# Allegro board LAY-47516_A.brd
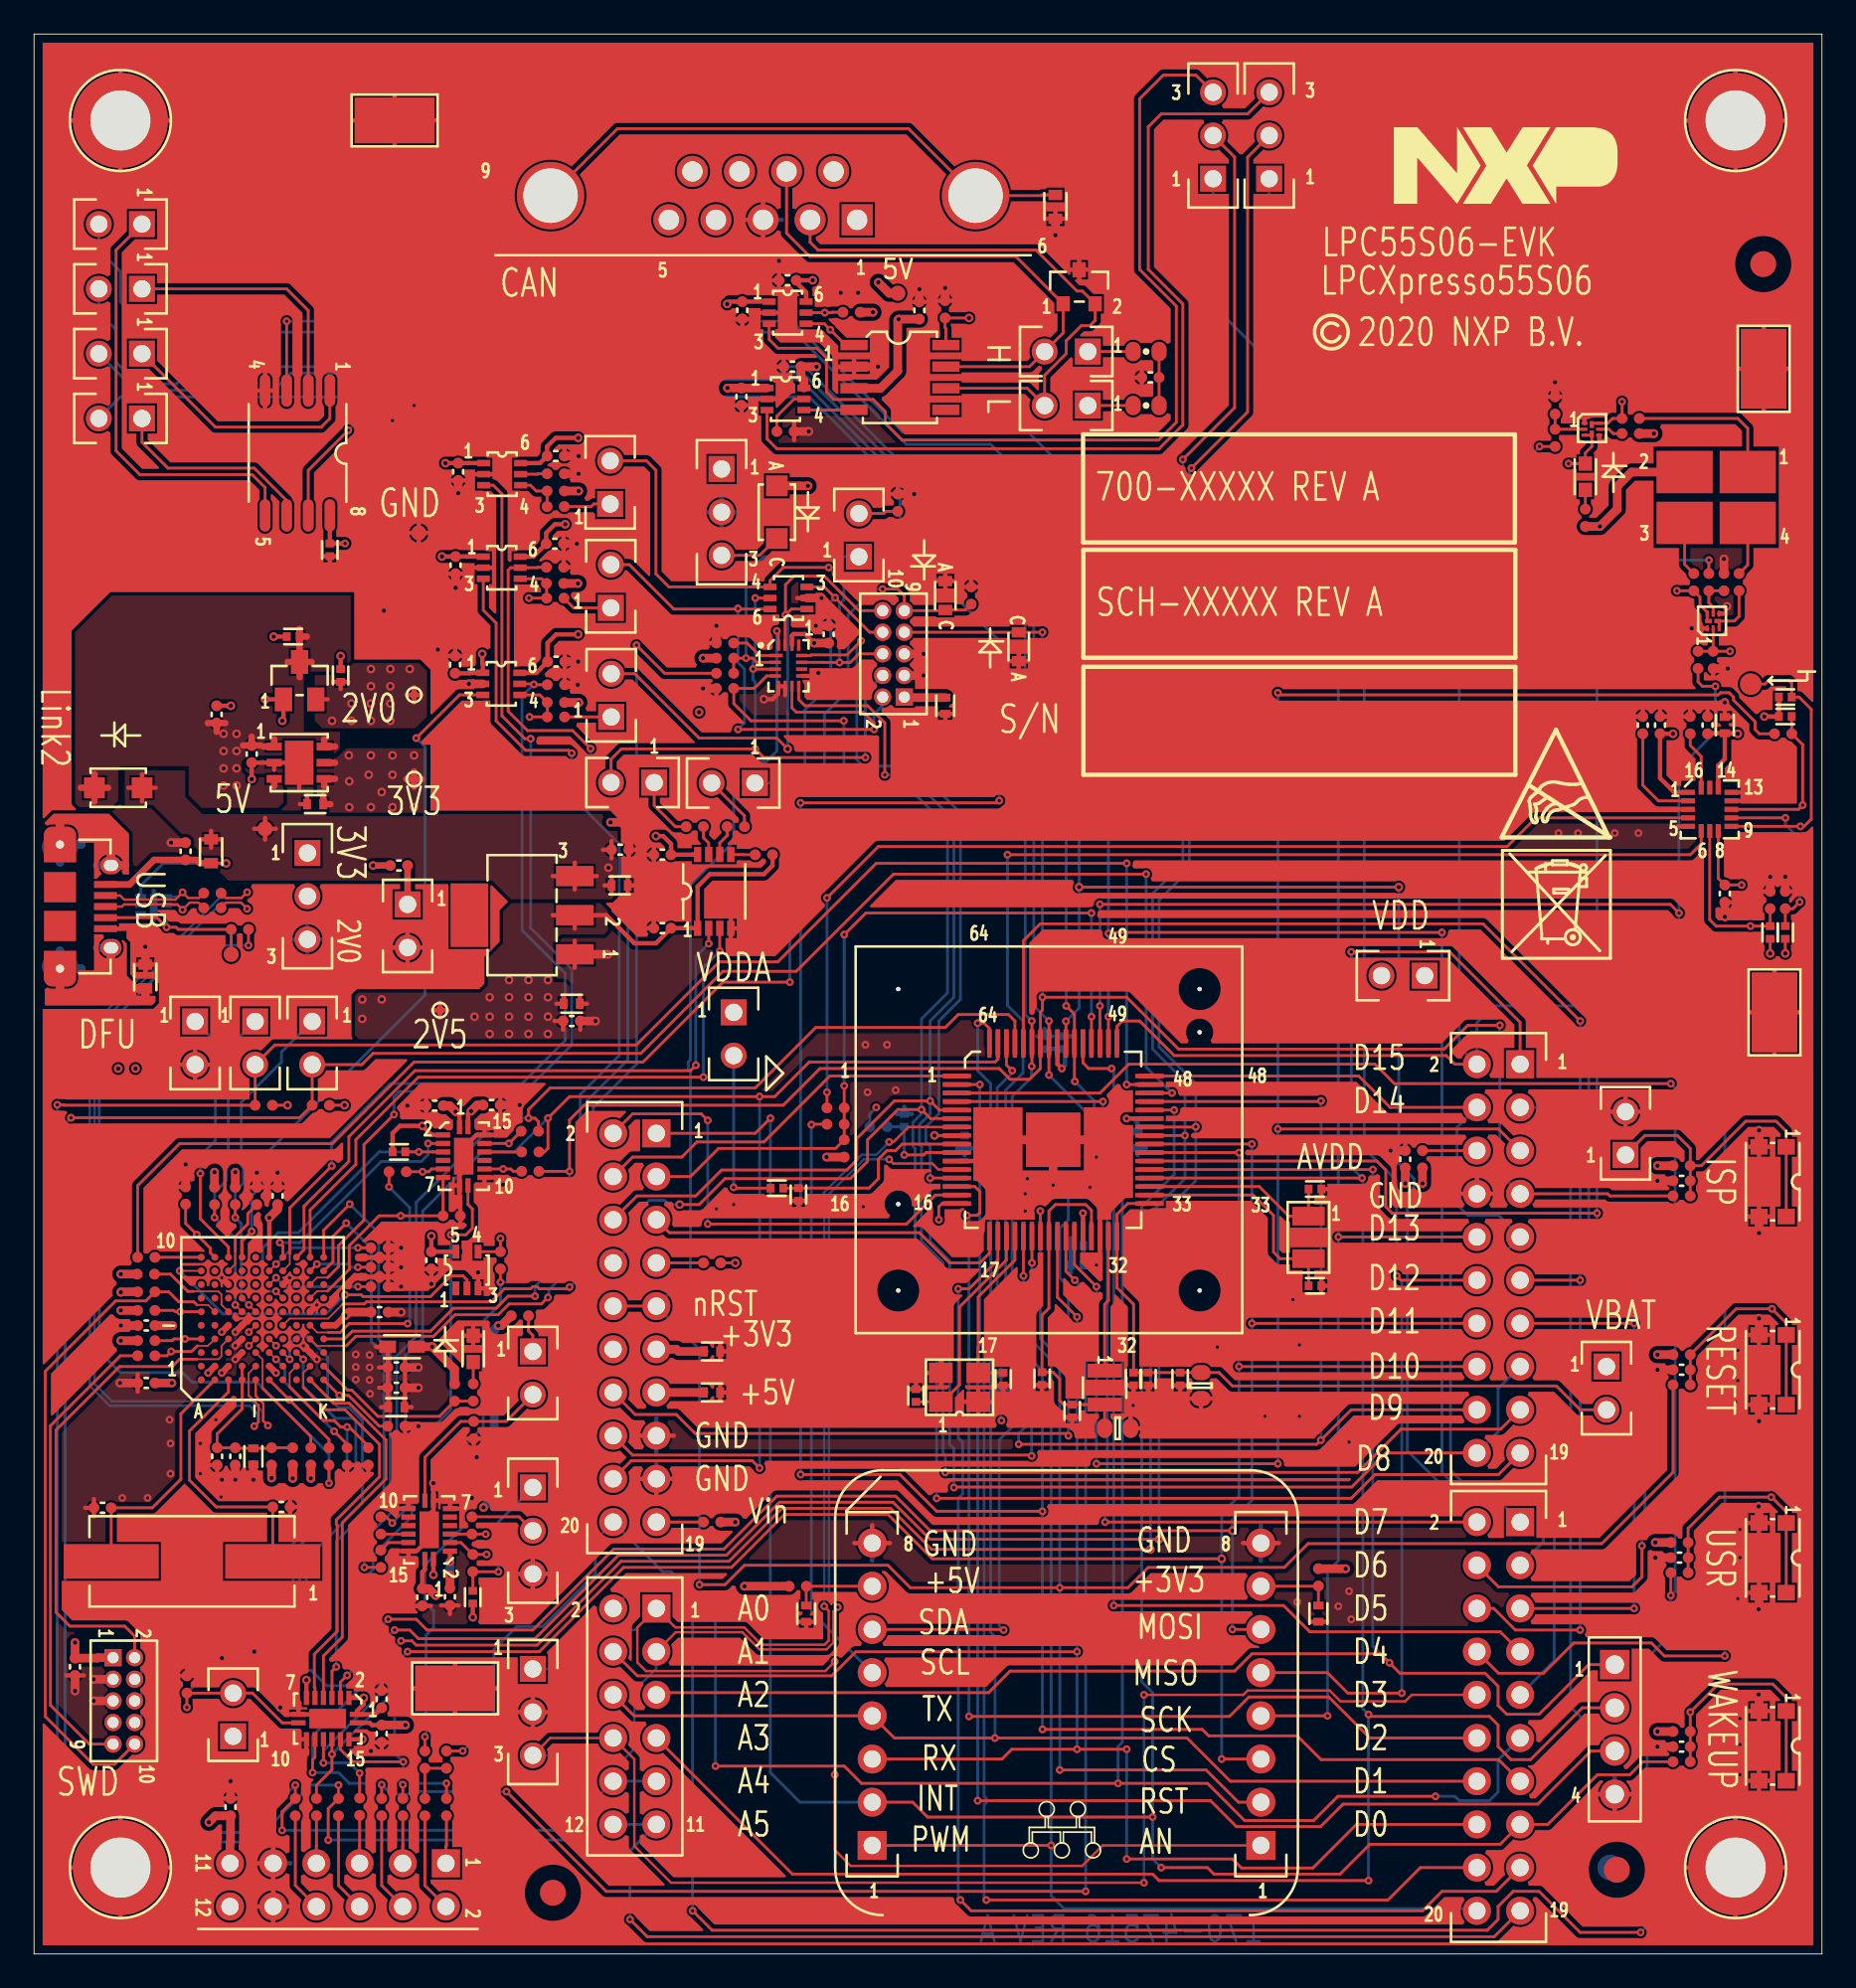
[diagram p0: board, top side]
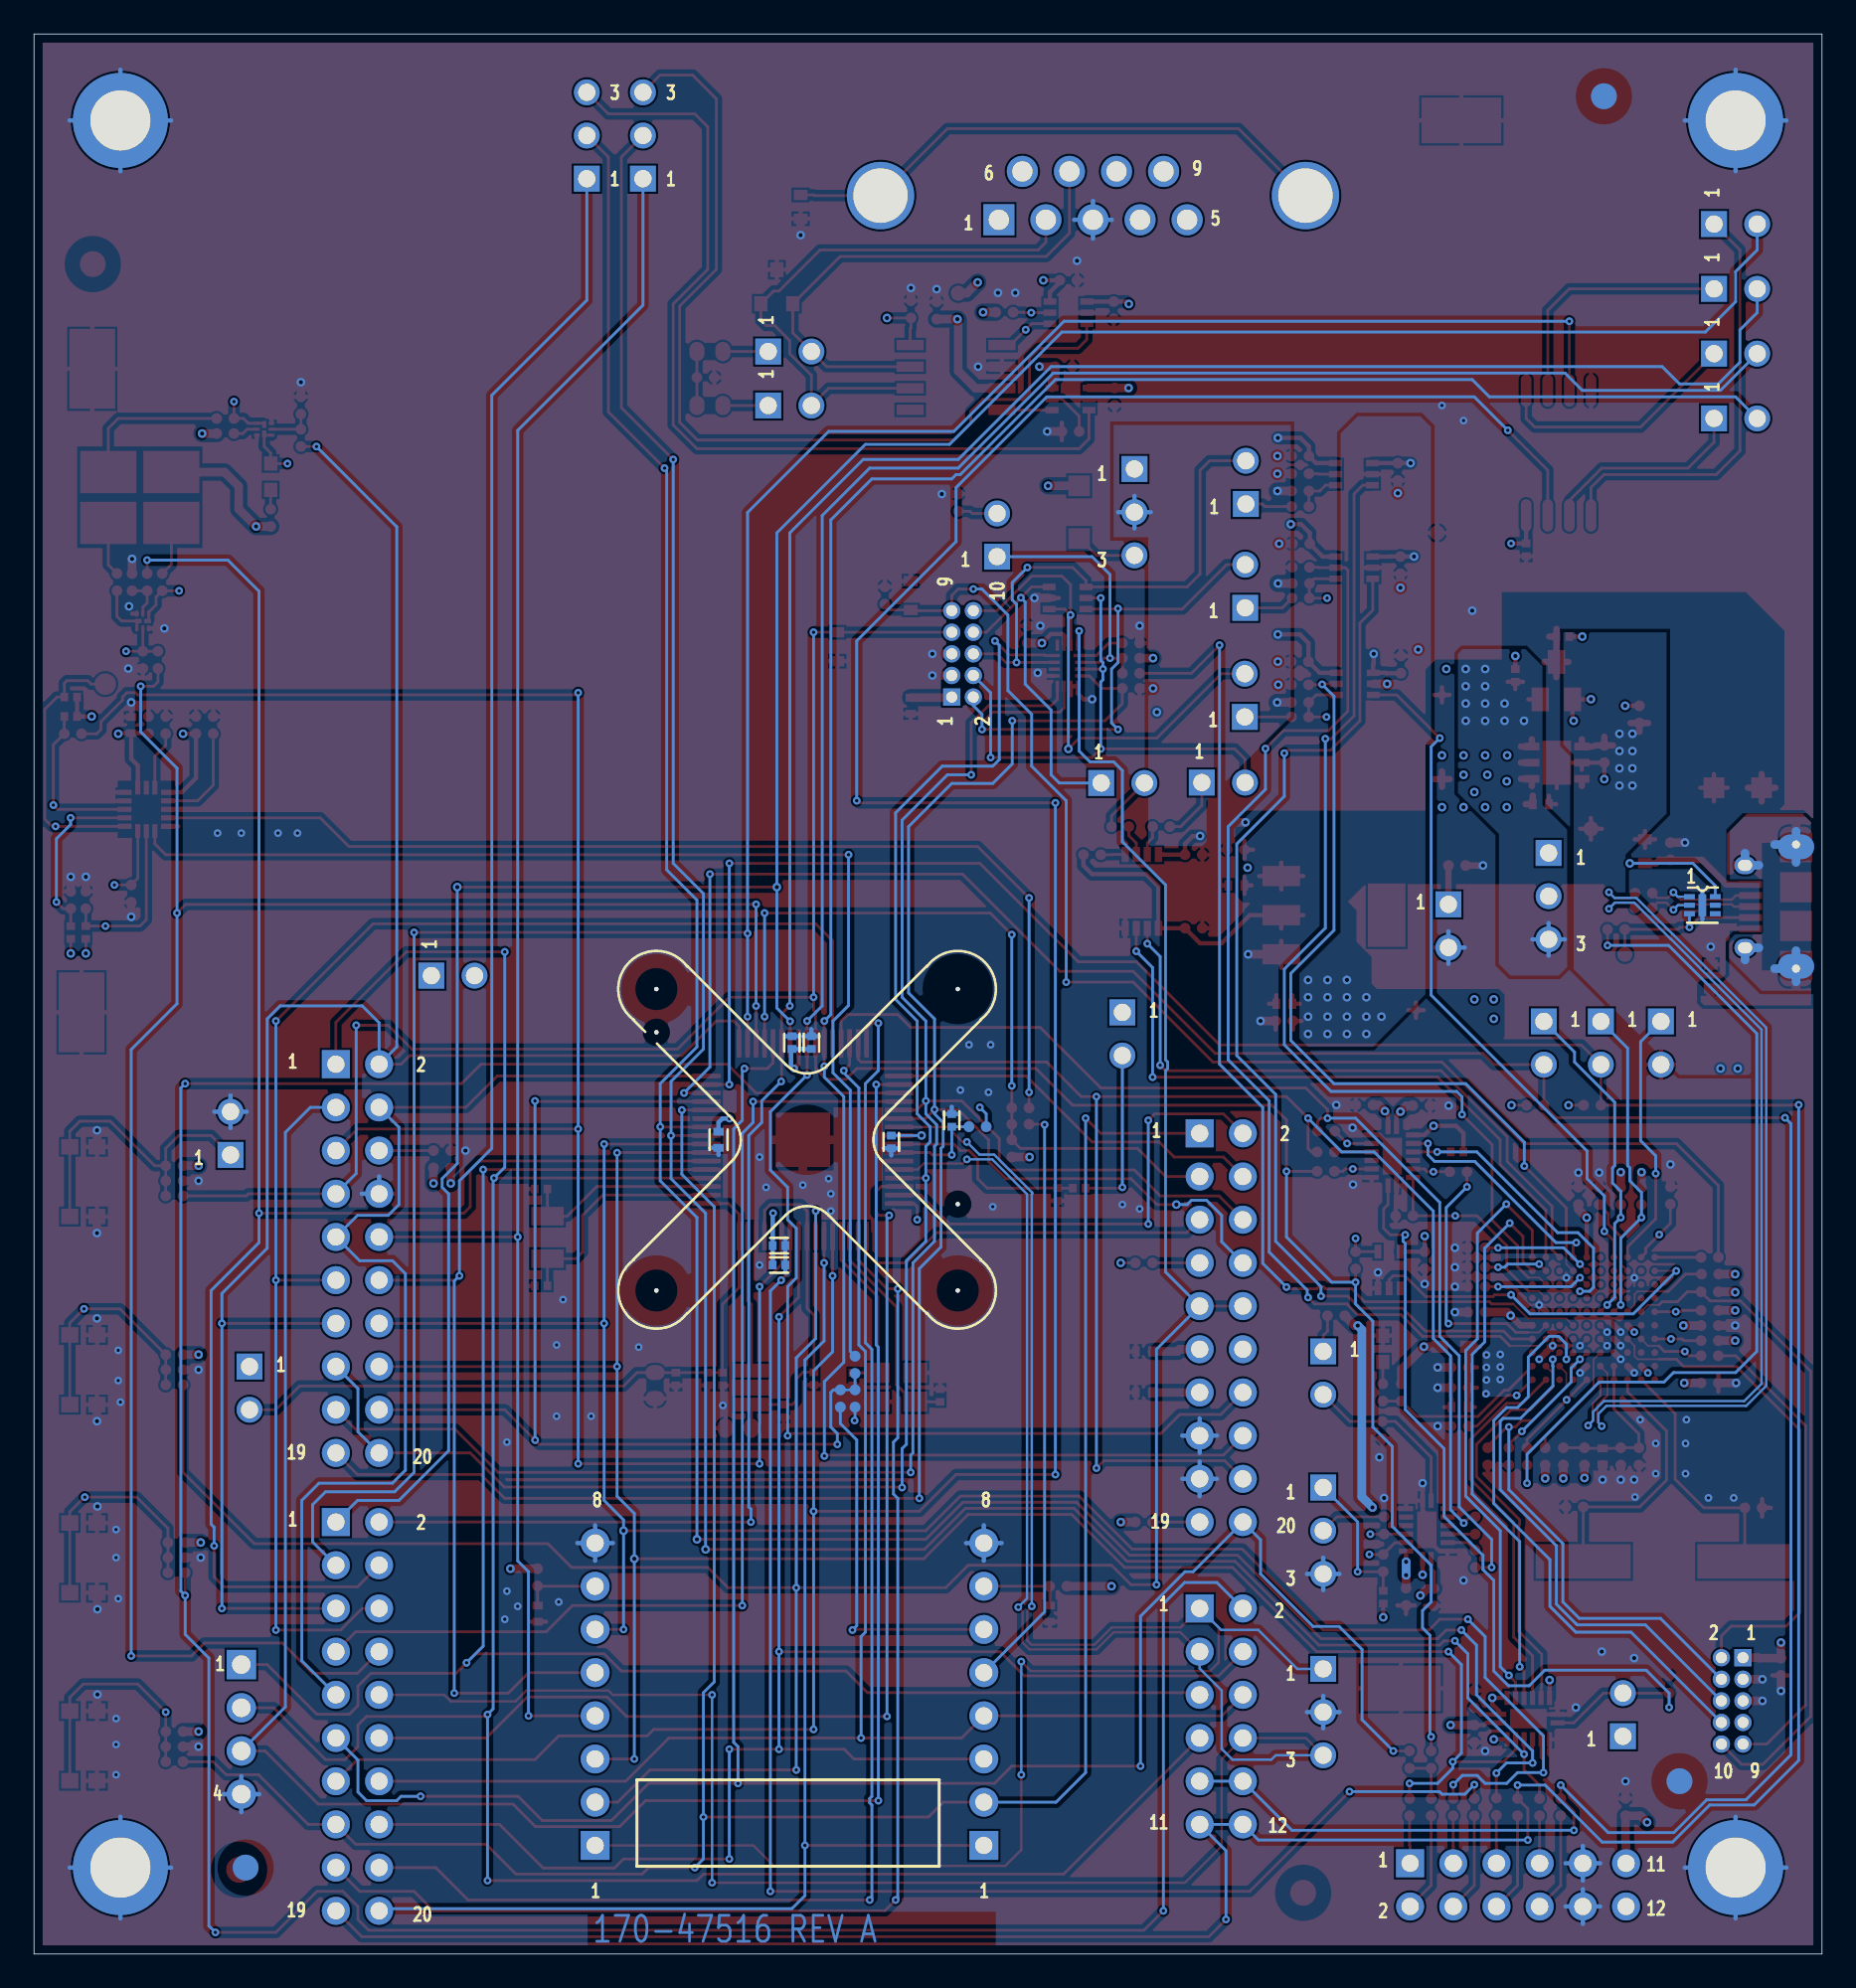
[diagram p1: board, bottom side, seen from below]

Outline 105.16 x 112.9 mm; copper layers: TOP, L2_GND_1, L3_PWR_1, BOTTOM. Coordinates in mm from the lower left corner of the outline.
Outline path: 0,112.9 0,0 105.16,0 105.16,112.9 0,112.9

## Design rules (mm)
constraint set DEFAULT: min track width 0.102
net group ARD_ADC0: nets ARD_ADC0_0_P ARD_MIK_ADC0_8_N
net group CON_DP2: nets N00991 N01033
net group FL_USB0_D: nets FL_USB0_DM FL_USB0_DP

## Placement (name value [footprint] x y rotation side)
C1  2.2UF  [CC0402_25]  8.92 64.85 90 top
C2  4.7UF  [CC0402_TOL0P15]  34.45 62.84 0 top
C3  0.1UF  [CC0402_25]  34.47 64.94 0 top
C4  4.7UF  [CC0402_TOL0P15]  31.62 55.88 0 top
C5  0.1UF  [CC0402_25]  31.62 54.86 0 top
C6  2.2UF  [CC0402_25]  12.8 70.56 270 top
C7  10uF  [CC0402_TOL0P2]  16.54 67.61 180 top
C8  2.2UF  [CC0402_25]  21.46 64.01 180 top
C10  2.2UF  [CC0402_25]  10.74 72.89 90 top
C11  1.0UF  [0402_CC]  15.24 77.47 180 top
C12  1.0UF  [0402_CC]  18.03 75.18 90 top
C18  0.1UF  [0402_CC]  61.06 31.93 270 top
C19  1.0UF  [0402_CC]  59.28 33.84 270 top
C22  0.1UF  [CC0402_25]  24.46 21.01 270 top
C23  0.1UF  [CC0402_25]  52.07 96.64 90 top
C24  0.1UF  [CC0402_25]  22.83 20.98 270 top
C25  1000pF  [CC0402_25]  65.66 92.71 180 top
C27  4.7UF  [CC0402_TOL0P15]  99.44 72.26 90 top
C28  0.1UF  [CC0402_25]  98.42 72.26 90 top
C29  0.1UF  [CC0402_25]  95.63 72.26 90 top
C30  0.1UF  [CC0402_25]  99.44 62.36 270 top
C31  0.1UF  [CC0402_25]  94.61 72.26 90 top
C32  0.01UF  [CC0402_25]  96.9 12.19 180 top
C33  0.01UF  [CC0402_25]  96.9 34.36 180 top
C34  0.01UF  [CC0402_25]  96.77 23.31 180 top
C55  10uF  [CC0402_TOL0P2]  75.54 20.02 270 top
C56  10uF  [CC0402_TOL0P2]  45.42 20.02 270 top
C57  4.7UF  [CC0402_TOL0P15]  39.88 33.02 0 top
C58  0.1UF  [CC0402_25]  80.64 46.74 90 top
C59  4.7UF  [CC0402_TOL0P15]  39.88 35.43 0 top
C69  0.1UF  [CC0402_25]  6.6 36.96 180 top
C70  0.1UF  [CC0402_25]  20.32 37.74 0 top
C71  0.1UF  [CC0402_25]  14.33 44.58 90 top
C72  0.1UF  [CC0402_25]  6.6 33.58 180 top
C73  0.1UF  [CC0402_25]  21.31 34.49 0 top
C74  0.1UF  [CC0402_25]  21.31 33.3 0 top
C75  4.7UF  [CC0402_TOL0P15]  21.31 32.16 0 top
C76  0.1UF  [CC0402_25]  11.84 29.26 270 top
C77  0.1UF  [CC0402_25]  10.77 29.26 270 top
C78  10uF  [CC0402_TOL0P2]  12.9 29.26 270 top
C79  27PF  [CC0402_25]  4.03 26.24 180 top
C80  27PF  [CC0402_25]  14.55 26.29 0 top
C81  0.1UF  [CC0402_25]  2.41 16.89 270 top
C82  0.1UF  [CC0402_25]  36.96 60.32 180 top
C83  0.1UF  [CC0402_25]  36.96 64.64 180 top
C84  0.1UF  [CC0402_25]  46.74 77.6 90 top
C85  0.1UF  [CC0402_25]  24.95 87.16 270 top
C86  0.1UF  [CC0402_25]  30.68 88.09 0 top
C87  0.1UF  [CC0402_25]  30.63 82.93 0 top
C88  0.1UF  [CC0402_25]  24.79 81.67 270 top
C89  10uF  [CC0402_TOL0P2]  53.59 73.41 270 top
C90  0.1UF  [CC0402_25]  24.77 75.82 90 top
C91  0.1UF  [CC0402_25]  30.71 76 0 top
C92  0.1UF  [CC0402_25]  23.57 49.89 180 top
C93  0.1UF  [CC0402_25]  26.91 49.93 0 top
C94  0.1UF  [CC0402_25]  23.37 40.79 270 top
C95  0.1UF  [CC0402_25]  11.56 8.64 90 top
C96  0.1UF  [CC0402_25]  20.45 14.99 90 top
C97  0.1UF  [CC0402_25]  20.45 12.95 270 top
C98  0.01UF  [CC0402_25]  96.9 45.47 180 top
C442  0.1UF  [CC0402_25]  41.61 91.58 270 top
C443  0.1UF  [CC0402_25]  44.6 93.34 180 top
C444  0.1UF  [CC0402_25]  41.66 96.66 270 top
C445  0.1UF  [CC0402_25]  44.32 98.42 180 top
C446  4.7UF  [CC0402_TOL0P15]  64.9 47.88 270 bottom
C447  1.0UF  [0402_CC]  61.34 40.51 180 bottom
C448  1.0UF  [0402_CC]  59.44 53.59 90 bottom
C449  1.0UF  [0402_CC]  60.58 53.59 90 bottom
C450  0.1UF  [0402_CC]  61.34 41.66 180 bottom
C451  0.1UF  [0402_CC]  54.74 47.75 270 bottom
C457  0.1UF  [0402_CC]  65.52 33.81 270 top
C458  47PF  [0402_CC]  67.41 33.81 270 top
C459  22UF  [CC0603_OV]  68.63 33.43 270 top
C460  0.1UF  [0402_CC]  44.96 44.67 270 top
C461  22UF  [CC0603_OV]  63.73 30.92 0 top
C462  12PF  [0402_CC]  57 33.81 270 top
C463  12PF  [0402_CC]  51.87 32.84 90 top
C464  12PF  [0402_CC]  75.34 39.29 0 top
C465  12PF  [0402_CC]  75.34 44.98 0 top
C466  0.1UF  [0402_CC]  17.4 82.57 270 top
C467  0.1UF  [0402_CC]  64.67 33.81 270 top
C468  0.1UF  [0402_CC]  51.18 49.02 90 bottom
D1  PMEG4010ER,115  [SOD123W]  4.95 68.58 0 top
D3  PESD1CAN  [SOT23_A]  61.47 98.04 0 top
D4  OVSARGB4R8  [LED4_0P4_3P4X3MM]  98.93 85.65 0 top
D5  RED  [LED_0603]  91.24 86.87 90 top
D8  RED  [LED_0603]  25.83 35.59 90 top
D9  PMEG1020EH  [SOD123LF]  43.69 84.79 90 top
D10  PESD3V3S1UB  [SOD523]  53.59 79.88 90 top
D11  PESD3V3L5UY  [SOT-363_0P65_SMT]  44.37 79.74 180 top
D12  PESD3V3S1UB  [SOD523]  57.91 76.87 270 top
J1  ZX62D-B-5PA8(30)  [CON9_MICROB_USB_SHELL_TH]  1.53 61.59 270 top
J3  HDR_1X3  [HDR103]  29.34 27.43 0 top
J7  CON SKT 8  [CON_1X8_SKT_2P54_TH]  72.15 6.39 180 top
J8  CON SKT 8  [CON_1X8_SKT_2P54_TH]  49.29 6.39 180 top
J9  CON_2X10  [CON_SKT2X10_TH]  87.4 52.32 0 top
J10  CON_2X10  [CON_SKT2X10_TH]  36.6 48.26 0 top
J11  HDR 1X4  [HDR1X4_2P54_TH]  92.96 17.02 0 top
J12  CON_2X10  [CON_SKT2X10_TH]  87.4 25.4 0 top
J13  SKT_2X6  [CON_2X6_SKT_100_TH]  36.6 20.32 270 top
J16  HDR 2X5  [HDR205_50_TH]  4.65 17.42 270 top
J17  HDR 2X5  [HDR205_50_TH]  51.18 73.91 90 top
J18  PPPC062LJBN-RC  [SKT2X6_100_TH_RA]  24.22 5.33 270 top
J19  DB9  [CON_DB9S_TH_RA_318]  37.34 101.98 180 top
J32  SKT_QFN64  [SKT_QFP64_0P5_22P25SQ_MM]  59.69 47.88 0 top
JP1  HDR_1X3  [HDR103]  16.08 64.74 0 top
JP4  HDR_1X3  [HDR103]  29.34 16.76 0 top
JP6  HDR 1X2  [HDR102]  9.47 54.84 0 top
JP7  HDR 1X2  [HDR102]  48.51 82.17 180 top
JP8  HDR_1X3  [HDR103]  40.44 87.33 0 top
JP9  HDR 1X2  [HDR102]  11.71 12.8 180 top
JP12  HDR 1X2  [HDR102]  29.34 35.43 0 top
JP13  HDR 1X2  [HDR102]  36.47 68.88 270 top
JP14  HDR 1X2  [HDR102]  42.39 68.86 270 top
JP15  HDR 1X2  [HDR102]  33.88 85.27 180 top
JP16  HDR 1X2  [HDR102]  33.92 79.16 180 top
JP17  HDR 1X2  [HDR102]  33.95 72.75 180 top
JP20  HDR 1X2  [HDR102]  81.79 57.53 270 top
JP21  HDR 1X2  [HDR102]  41.15 55.37 0 top
JP22  HDR 1X2  [HDR102]  92.48 34.54 0 top
JP23  HDR 1X2  [HDR102]  61.98 94.23 270 top
JP24  HDR 1X2  [HDR102]  61.98 91.06 270 top
JP25  HDR_1X3  [HDR103]  72.64 104.39 180 top
JP26  HDR_1X3  [HDR103]  69.34 104.39 180 top
JP27  HDR 1X2 TH  [HDR_1X2]  6.35 97.92 270 top
JP28  HDR 1X2 TH  [HDR_1X2]  6.35 101.73 270 top
JP29  HDR 1X2 TH  [HDR_1X2]  6.35 94.11 270 top
JP30  HDR 1X2 TH  [HDR_1X2]  6.35 90.3 270 top
JS1  HDR 1X2  [HDR102]  21.97 61.72 0 top
JS3  HDR 1X2  [HDR102]  93.6 46.99 180 top
JS4  HDR 1X2  [HDR102]  13 54.84 0 top
JS5  HDR 1X2  [HDR102]  16.36 54.84 0 top
L1  330 OHM  [IND_1608]  10.41 64.85 90 top
L2  330 OHM  [IND_1608]  6.55 57.48 90 top
L7  330 OHM  [IND_1608]  60.07 102.74 270 top
L10  600OHM  [IND_1P8X1MM_SM]  21.64 35.71 180 top
L11  4.7uH  [IND2_2722]  62.97 33.31 270 top
NOREF  -  []  12.9 28.79 90 top
NOREF#2  -  []  35.02 62.51 90 top
NOREF#3  -  []  105.05 14.34 90 top
NOREF#4  -  []  39.3 35.11 0 top
NOREF#5  -  []  22.02 26.19 0 top
NOREF#6  -  []  15.55 13.59 90 top
NOREF#7  -  []  97.08 84.15 0 top
NOREF#8  -  []  21.89 31.83 90 top
NOREF#9  -  []  86.36 58.55 0 top
NOREF#10  -  []  100.85 25.4 0 top
NOREF#11  -  []  70.88 36.69 90 top
NOREF#12  -  []  101.45 21.25 90 top
NOREF#13  -  []  56.19 42.13 0 top
NOREF#14  -  []  37.34 101.98 0 top
NOREF#15  -  []  37.95 16.73 0 top
NOREF#16  -  []  53.24 74.01 0 top
NOREF#17  -  []  99.44 71.79 90 top
NOREF#18  -  []  6.23 65.34 90 top
NOREF#19  -  []  22.42 14.27 0 top
NOREF#20  -  []  62.97 32.31 90 top
NOREF#21  -  []  50.83 39.02 90 top
NOREF#22  -  []  50.83 39.02 0 top
NOREF#23  -  []  51.18 73.91 90 top
NOREF#24  -  []  5.08 5.08 0 top
NOREF#25  -  []  -283.21 262.64 0 top
NOREF#26  -  []  20.8 35.71 0 top
NOREF#27  -  []  24.54 26.74 0 top
NOREF#28  -  []  18.53 1.29 90 top
NOREF#29  -  []  101.45 32.31 90 top
NOREF#30  -  []  105.05 25.4 90 top
NOREF#31  -  []  27.3 87.12 90 top
NOREF#32  -  []  53.59 72.93 90 top
NOREF#33  -  []  75.19 20.62 0 top
NOREF#34  -  []  63.69 42.13 90 top
NOREF#35  -  []  92.18 7.98 0 top
NOREF#36  -  []  27.14 26.74 90 top
NOREF#37  -  []  16.02 12.62 90 top
NOREF#38  -  []  22.02 23.69 90 top
NOREF#39  -  []  37.34 101.98 90 top
NOREF#40  -  []  100.92 71.69 90 top
NOREF#41  -  []  86.33 65.66 0 top
NOREF#42  -  []  97.05 65.81 0 top
NOREF#43  -  []  9.83 2.84 0 top
NOREF#44  -  []  65.22 48.45 0 top
NOREF#45  -  []  26.49 45.66 90 top
NOREF#46  -  []  22.02 23.69 90 top
NOREF#47  -  []  92.96 14.48 90 top
NOREF#48  -  []  26.57 45.11 90 top
NOREF#49  -  []  100.38 90.87 0 top
NOREF#50  -  []  79.98 102.92 0 top
NOREF#51  -  []  22.54 35.21 0 top
NOREF#52  -  []  16.02 12.62 0 top
NOREF#53  -  []  22.99 26.66 0 top
NOREF#54  -  []  23.97 45.11 0 top
NOREF#55  -  []  98.76 78.82 0 top
NOREF#56  -  []  -31.65 -177.57 0 top
NOREF#57  -  []  26.49 47.66 90 top
NOREF#58  -  []  99.77 71.69 0 top
NOREF#59  -  []  21.68 5.33 0 top
NOREF#60  -  []  61.7 83.01 0 top
NOREF#61  -  []  74.94 52.88 90 top
NOREF#62  -  []  100.05 65.81 90 top
NOREF#63  -  []  64.94 52.88 0 top
NOREF#64  -  []  34.06 7.62 0 top
NOREF#65  -  []  103.71 53.02 90 top
NOREF#66  -  []  100.38 77.86 90 top
NOREF#67  -  []  30.38 103.4 90 top
NOREF#68  -  []  9.83 1.29 0 top
NOREF#69  -  []  39.3 32.69 0 top
NOREF#70  -  []  76.3 95.35 0 top
NOREF#71  -  []  97.43 83.95 0 top
NOREF#72  -  []  -169.51 -124.45 0 top
NOREF#73  -  []  98.05 66.03 90 top
NOREF#74  -  []  101.45 32.31 0 top
NOREF#75  -  []  33.87 62.51 0 top
NOREF#76  -  []  49.91 73.91 0 top
NOREF#77  -  []  4.65 12.34 90 top
NOREF#78  -  []  12.55 29.86 0 top
NOREF#79  -  []  52.32 73.09 90 top
NOREF#80  -  []  61.72 76.23 0 top
NOREF#81  -  []  46.27 20.62 90 top
NOREF#82  -  []  99.83 66.31 90 top
NOREF#83  -  []  25.02 45.19 0 top
NOREF#84  -  []  53.94 16.73 90 top
NOREF#85  -  []  101.45 43.37 0 top
NOREF#86  -  []  20.84 32.16 0 top
NOREF#87  -  []  69.7 5.16 0 top
NOREF#88  -  []  34.06 15.24 90 top
NOREF#89  -  []  92.14 89.09 90 top
NOREF#90  -  []  101.45 10.19 90 top
NOREF#91  -  []  18.07 15.14 90 top
NOREF#92  -  []  0 112.9 0 top
NOREF#93  -  []  -162.48 -109.39 0 top
NOREF#94  -  []  47.03 104.82 90 top
NOREF#95  -  []  18.02 12.62 0 top
NOREF#96  -  []  54.34 51.63 0 top
NOREF#97  -  []  54.44 74.01 90 top
NOREF#98  -  []  40.45 32.69 90 top
NOREF#99  -  []  3.51 18.25 90 top
NOREF#100  -  []  33.97 62.84 0 top
NOREF#101  -  []  101.45 21.25 0 top
NOREF#102  -  []  98.05 66.03 0 top
NOREF#103  -  []  46.12 26.87 0 top
NOREF#104  -  []  99.83 66.31 90 top
NOREF#105  -  []  38.72 104.82 90 top
NOREF#106  -  []  30.38 103.4 0 top
NOREF#107  -  []  45.07 20.62 0 top
NOREF#108  -  []  97.28 66.31 0 top
NOREF#109  -  []  -162.48 -109.39 0 top
NOREF#110  -  []  52.32 73.09 0 top
NOREF#111  -  []  100.04 68.81 0 top
NOREF#112  -  []  4.2 60.94 90 top
NOREF#113  -  []  68.55 54.2 90 top
NOREF#114  -  []  23.56 106.47 0 top
NOREF#115  -  []  6.35 67.63 90 top
NOREF#116  -  []  56.19 42.28 0 top
NOREF#117  -  []  101.45 43.37 90 top
NOREF#118  -  []  17.14 67.96 0 top
NOREF#119  -  []  92.05 89.31 90 top
NOREF#120  -  []  -134.06 -104.24 0 top
NOREF#121  -  []  99.33 77.86 0 top
NOREF#122  -  []  99.11 77.95 90 top
NOREF#123  -  []  34.06 7.62 90 top
NOREF#124  -  []  5.08 5.08 0 top
NOREF#125  -  []  26.25 106.47 90 top
NOREF#126  -  []  -309.88 -258.44 0 top
NOREF#127  -  []  0 0 0 top
NOREF#128  -  []  73.26 26.87 90 top
NOREF#129  -  []  105.16 0 90 top
NOREF#130  -  []  39.4 33.02 0 top
NOREF#131  -  []  65.69 44.13 90 top
NOREF#132  -  []  66.37 48.45 90 top
NOREF#133  -  []  16.06 67.61 0 top
NOREF#134  -  [unnamed#2]  93.09 4.95 0 top
NOREF#135  -  []  61.72 69.34 0 top
NOREF#136  -  []  4.2 60.29 90 top
NOREF#137  -  []  20.74 31.83 0 top
NOREF#138  -  []  24.05 45.66 0 top
NOREF#139  -  []  4.65 17.42 0 top
NOREF#140  -  []  54.34 44.13 0 top
NOREF#141  -  []  91.09 89.09 0 top
NOREF#142  -  []  -1.27 70.94 0 top
NOREF#143  -  []  4.53 59.17 90 top
NOREF#144  -  []  75.54 19.54 90 top
NOREF#145  -  []  101.45 10.19 0 top
NOREF#146  -  []  3.51 18.25 0 top
NOREF#147  -  []  3.15 81.28 0 top
NOREF#148  -  []  32.2 55.55 90 top
NOREF#149  -  []  13.75 29.86 90 top
NOREF#150  -  []  11.52 2.79 90 top
NOREF#151  -  []  39.4 35.43 0 top
NOREF#152  -  []  5.08 5.08 0 top
NOREF#153  -  []  45.42 19.54 90 top
NOREF#154  -  []  -169.51 -124.45 0 top
NOREF#155  -  []  51.18 73.91 90 top
NOREF#156  -  []  4.65 16.15 90 top
NOREF#157  -  []  48.5 36.69 0 top
NOREF#158  -  []  100.85 36.46 0 top
NOREF#159  -  []  0 0 0 top
NOREF#160  -  []  22.42 14.27 90 top
NOREF#161  -  []  22.54 34.21 90 top
NOREF#162  -  []  105.05 47.52 90 top
NOREF#163  -  []  99.83 66.31 90 top
NOREF#164  -  []  56.19 42.13 0 top
NOREF#165  -  []  54.19 44.13 0 top
NOREF#166  -  []  40.45 35.11 90 top
NOREF#167  -  []  105.05 36.46 90 top
NOREF#168  -  []  -134.06 -104.24 0 top
NOREF#169  -  []  100.79 84.15 90 top
NOREF#170  -  []  94.87 7.98 90 top
NOREF#171  -  []  3.55 67.63 0 top
NOREF#172  -  []  -3.84 87.12 0 top
NOREF#173  -  []  103.07 90.87 90 top
NOREF#174  -  []  100.43 83.95 90 top
NOREF#175  -  []  76.39 20.62 90 top
NOREF#176  -  []  64.9 47.4 90 top
NOREF#177  -  []  31.15 55.88 0 top
NOREF#178  -  [unnamed#2]  101.7 99.37 0 top
NOREF#179  -  [unnamed#2]  30.52 3.6 0 top
NOREF#180  -  []  100.85 47.52 0 top
NOREF#181  -  []  31.05 55.55 0 top
NOREF#182  -  []  101.02 53.02 0 top
NOREF#183  -  []  91.18 89.31 0 top
NOREF#184  -  []  65.69 44.13 90 top
NOREF#185  -  []  18.34 67.96 90 top
NOREF#186  -  []  15.47 15.14 0 top
NOREF#187  -  []  0.58 -33.6 0 top
NOREF#188  -  []  100.85 14.34 0 top
NOREF#189  -  []  99.05 66.03 90 top
NOREF#190  -  []  69.7 5.16 180 bottom
NOREF#191  -  [unnamed#2]  12.83 109.24 180 bottom
NOREF#192  -  [unnamed#2]  8.38 10.16 180 bottom
NOREF#193  -  [unnamed#2]  92.71 5.08 180 bottom
Q4  PMDXB600UNEZ  [DFN1010N-6_0P35_1P15X1P05]  98.76 78.38 90 top
Q5  PMDXB600UNEZ  [DFN1010N-6_0P35_1P15X1P05]  91.62 89.66 0 top
R1  0  [RC0402_25]  10.49 62.38 0 top
R2  0  [RC0402_25]  10.49 61.52 0 top
R3  0  [RC0402_25]  12.11 60.25 0 top
R19  100K  [RC0402_25]  48.08 96.54 180 top
R20  10K  [0402_CC]  25.81 20.98 90 top
R21  60.4  [RC0603_OV]  65.41 94.23 0 top
R23  100  [RC0402_25]  25.81 22.99 90 top
R24  0  [RC0402_25]  20.4 23.24 270 top
R25  100  [RC0402_25]  25.76 25.2 270 top
R26  0  [RC0402_25]  20.4 25.2 90 top
R27  60.4  [RC0603_OV]  65.41 91.06 0 top
R28  100K  [RC0402_25]  25.86 30.81 270 top
R29  2.2K  [RC0402_25]  53.58 96.71 90 top
R30  510  [RC0402_25]  97.61 80.67 270 top
R31  680  [RC0402_25]  100.28 80.67 270 top
R32  10K  [0402_CC]  103 73.91 0 top
R33  10K  [0402_CC]  103 72.77 0 top
R34  10K  [0402_CC]  102.11 60.07 90 top
R35  10K  [0402_CC]  103 60.07 90 top
R36  100  [RC0402_25]  102.87 71.75 0 top
R37  510  [RC0402_25]  91.24 84.45 90 top
R38  510  [RC0402_25]  93.9 90.3 180 top
R39  2.2K  [RC0402_25]  102.11 61.98 90 top
R40  2.2K  [RC0402_25]  103 61.98 90 top
R41  1M  [RC0402_25]  97.41 72.26 90 top
R42  2.2K  [RC0402_25]  93.9 89.41 0 top
R43  330K  [RC0402_25]  96.9 13.08 0 top
R44  100K  [RC0402_25]  96.9 35.24 0 top
R45  100K  [RC0402_25]  96.77 24.2 0 top
R46  1K  [RC0402_25]  96.9 11.3 180 top
R47  1K  [RC0402_25]  96.77 22.42 180 top
R48  1K  [RC0402_25]  96.9 33.47 180 top
R60  0  [RC0402_25]  39.88 25.4 180 top
R61  0  [RC0402_25]  81.66 46.74 270 top
R62  0  [RC0402_25]  39.88 40.64 180 top
R65  0  [RC0402_25]  49.66 48.65 0 bottom
R74  2.2K  [RC0402_25]  47.65 47.37 90 top
R75  2.2K  [RC0402_25]  56.87 32.67 90 bottom
R77  0  [RC0402_25]  47.14 49.76 180 top
R80  0  [RC0402_25]  47.14 48.79 180 top
R84  0  [RC0402_25]  56.87 34.65 90 bottom
R88  0  [RC0402_25]  57.73 32.67 270 bottom
R91  2.2K  [RC0402_25]  10.62 44.58 270 top
R92  2.2K  [RC0402_25]  11.84 44.58 270 top
R93  0  [RC0402_25]  17.35 29.26 270 top
R94  470  [RC0402_25]  16.28 29.26 270 top
R95  12.1K  [RC0402_25]  18.41 29.26 270 top
R96  12.1K  [RC0402_25]  6.6 37.85 0 top
R97  100K  [RC0402_25]  6.6 36.07 0 top
R98  12.1K  [RC0402_25]  6.6 38.94 0 top
R99  2.2K  [RC0402_25]  21.31 31.04 180 top
R100  2.2K  [RC0402_25]  6.58 39.98 0 top
R101  2.2K  [RC0402_25]  8.92 44.6 270 top
R102  2.2K  [RC0402_25]  19.66 29.26 270 top
R103  1.5K  [RC0402_25]  6.6 40.97 0 top
R104  0  [RC0402_25]  6.6 35.18 0 top
R105  2.2K  [RC0402_25]  24.74 33.02 270 top
R106  2.2K  [RC0402_25]  25.83 33.02 90 top
R107  2.2K  [RC0402_25]  20.32 40.39 0 top
R108  2.2K  [RC0402_25]  20.32 41.53 0 top
R109  2.2K  [RC0402_25]  20.32 39.24 0 top
R110  2.2K  [RC0402_25]  13.11 44.58 90 top
R111  100  [RC0402_25]  38.86 66.29 180 top
R112  100  [RC0402_25]  41.27 66.29 0 top
R113  100K  [RC0402_25]  42.93 64.64 0 top
R114  0  [RC0402_25]  40.64 77.09 180 top
R115  100K  [RC0402_25]  40.64 74.42 180 top
R116  100K  [RC0402_25]  30.68 86.03 180 top
R117  100K  [RC0402_25]  40.64 76.2 180 top
R118  100  [RC0402_25]  30.68 85.12 0 top
R119  0  [RC0402_25]  40.64 75.31 180 top
R120  2.2K  [RC0402_25]  30.68 87.05 0 top
R121  2.2K  [RC0402_25]  50.8 85.34 90 top
R122  100K  [RC0402_25]  30.65 80.59 180 top
R123  100  [RC0402_25]  30.66 79.73 0 top
R124  2.2K  [RC0402_25]  30.65 81.55 0 top
R125  2.2K  [RC0402_25]  55.12 79.88 90 top
R126  100K  [RC0402_25]  30.7 73.6 180 top
R127  100  [RC0402_25]  30.7 72.75 0 top
R128  2.2K  [RC0402_25]  30.7 74.64 0 top
R129  10K  [0402_CC]  21.46 47.17 0 top
R130  0  [RC0402_25]  29.16 48.39 0 top
R131  0  [RC0402_25]  29.18 47.16 0 top
R132  2.2K  [RC0402_25]  21.39 46 180 top
R133  2.2K  [RC0402_25]  29.18 46.02 0 top
R134  2.2K  [RC0402_25]  24.56 43.41 0 top
R135  2.2K  [RC0402_25]  27.43 40.79 270 top
R136  0  [RC0402_25]  22.99 11.43 90 top
R137  0  [RC0402_25]  24.26 11.43 90 top
R138  100  [RC0402_25]  21.69 8.64 270 top
R139  100  [RC0402_25]  24.26 8.64 270 top
R140  100  [RC0402_25]  19.15 8.66 270 top
R141  100  [RC0402_25]  22.99 8.64 90 top
R142  100  [RC0402_25]  20.45 8.64 90 top
R143  100  [RC0402_25]  16.61 8.64 270 top
R144  100  [RC0402_25]  17.91 8.64 90 top
R145  100  [RC0402_25]  15.37 8.64 90 top
R146  2.2K  [RC0402_25]  8.99 15.85 90 top
R147  100K  [RC0402_25]  96.9 46.35 0 top
R148  2.2K  [RC0402_25]  13.51 49.91 180 top
R149  2.2K  [RC0402_25]  16.87 49.91 180 top
R150  1K  [RC0402_25]  96.9 44.58 180 top
R151  0  [RC0402_25]  15.21 29.26 90 top
R152  0  [RC0402_25]  13.97 29.26 90 top
R153  0  [RC0402_25]  75.54 22.15 270 top
R154  0  [RC0402_25]  44.92 21.63 0 top
R158  1K  [RC0402_25]  28.58 37.53 0 top
R159  2.2K  [RC0402_25]  44.2 89.53 0 top
R160  100K  [RC0402_25]  98.76 76.1 270 top
R161  100  [RC0402_25]  97.87 76.1 90 top
R162  100  [RC0402_25]  98.5 80.67 270 top
R163  100K  [RC0402_25]  99.39 80.67 90 top
R164  100  [RC0402_25]  89.46 89.15 90 top
R165  100K  [RC0402_25]  89.46 91.06 90 top
R166  0  [0402_CC]  43.69 45.03 0 top
SS1  .635" LONG  [SPACER_139T]  5.08 5.08 0 top
SS2  .635" LONG  [SPACER_139T]  100.08 5.08 0 top
SS3  .635" LONG  [SPACER_139T]  5.08 107.82 0 top
SS4  .635" LONG  [SPACER_139T]  100.08 107.82 0 top
SW1  KMR221NG LFS  [SW4_4P2X2P8_SM]  102.25 12.24 270 top
SW2  KMR221NG LFS  [SW4_4P2X2P8_SM]  102.25 34.36 270 top
SW3  KMR221NG LFS  [SW4_4P2X2P8_SM]  102.25 23.3 270 top
SW4  KMR221NG LFS  [SW4_4P2X2P8_SM]  102.25 45.42 270 top
TP1  TP_2P7X4P7  [TP_2P7X4P7MM]  101.73 93.22 0 top
TP2  TP_2P7X4P7  [TP_2P7X4P7MM]  102.36 55.37 0 top
TP3  TP_2P7X4P7  [TP_2P7X4P7MM]  21.21 107.82 90 top
TP4  TP_2P7X4P7  [TP_2P7X4P7MM]  24.77 15.62 270 top
TP5  TP_35MIL  [TESTPOINT_35MIL]  11.6 58.78 0 top
TP6  TP_35MIL  [TESTPOINT_35MIL]  50.8 97.66 0 top
TP7  TP_35MIL  [TESTPOINT_35MIL]  22.63 83.57 0 top
TP10  -  [TPAD_050]  100.97 74.68 0 top
TP11  -  [TPAD_020]  23.88 55.5 0 top
TP12  -  [TPAD_020]  22.35 69.09 0 top
TP13  -  [TPAD_020]  22.35 74.04 0 top
TP14  TP_35MIL  [TESTPOINT_35MIL]  13.59 66.17 0 top
U1  NCP1117ST25T3G  [SOT223]  28.7 61.09 90 top
U2  RClamp0854P.TCT  [SLP1616P6]  7.04 61.67 270 bottom
U3  NCP692MN33T2G  [DFN6_0P95_3X3]  15.6 70.05 0 top
U4  XC6203E202MR-G  [SOT-23]  15.62 74.88 0 top
U9  TJA1044GT  [SO8_1P27_4X5]  50.93 92.71 0 top
U11  74AVC4TD245BQ  [DHVQFN16_0P5_3P6X2P6]  23.24 24.94 180 top
U12  FXOS8700CQ  [QFN5X3_0P5_3X3]  98.55 67.31 0 top
U16  LPC4322JET100  [FBGA100_0P8_9X9]  13.44 37.37 90 top
U17  74AVC2T45DP  [MSOP_8P_0P65_3X3MM]  40 62.48 0 top
U18  NX3DV2567GU  [PQFN16_0P4_2P65X1P85]  44.37 75.76 270 top
U19  74LVC1T45GW,125  [SOT-363_0P65_SMT]  27.53 87.02 0 top
U20  74LVC1T45GW,125  [SOT-363_0P65_SMT]  27.51 81.52 0 top
U21  74LVC1T45GW,125  [SOT-363_0P65_SMT]  27.48 74.69 0 top
U22  74AVC4TD245BQ  [DHVQFN16_0P5_3P6X2P6]  25.27 46.91 0 top
U23  74LVC1G07GW-Q100  [SC70-5]  25.46 40.22 0 top
U24  74AVC4TD245BQ  [DHVQFN16_0P5_3P6X2P6]  17.27 13.84 270 top
U25  74LVC1T45GW,125  [SOT-363_0P65_SMT]  44.2 91.44 0 top
U26  74LVC1T45GW,125  [SOT-363_0P65_SMT]  44.32 96.52 0 top
U28  LPC55S06JBD64  [TQFP64_0P5_10X10_EP_3P31]  59.94 47.88 0 top
U29  MX25R8035FM2IL0  [SO8-25X75-200]  15.49 88.27 180 top
Y1  12MHZ  [XTL2_11P6X4P85_SM]  9.29 23.09 180 top
Y2  16MHZ  [XTAL_4_3P3X2P6MM]  54.43 33.32 0 top
Y3  32.768KHZ  [XTAL2-3P2X1P5-SM]  74.96 42.14 270 top

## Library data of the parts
C1-C8 C10-C12 C18 C19 C22-C25 C27-C34 C55-C59 C69-C98 C442-C451 C457-C468 = CAP_NP
D1 D9 = DIODE_SCHTKY
D3 = DIODE_BIDIR_3P
D4 = LED_GPLY6900
D5 D8 = LED
D10 D12 = DIODE_TVS
D11 = DIODE_ARRAY_5CH
J1 = MICRO_USB_CONN_9PIN
J3 JP1 JP4 JP8 JP25 JP26 = CONN_HDR_3X1
J7 J8 = CONN_HDR_8X1
J9 J10 J12 = CONN_HDR_10X2
J11 = CONN_HDR_4X1
J13 J18 = CONN_HDR_6X2
J16 J17 = CONN_HDR_5X2
J19 = CONN_DB9M_MTGTABS
J32 = QFPSOCKET65
JP6 JP7 JP9 JP12-JP17 JP20-JP24 JP27-JP30 JS1 JS3-JS5 = CONN_HDR_2X1
L1 L2 L7 = BEAD
L10 = INDUCTOR
L11 = INDUCTOR_FERRITE_A
Q4 Q5 = NMOS_DUAL_PMDXB600UNE_8P
R1-R3 R19 R21 R23-R48 R60-R62 R65 R74 R75 R77 R80 R84 R88 R91-R128 R130-R154 R158-R166 = RES
R20 R129 = RES: tolerance: 5%
SS1-SS4 = SPACER
SW1-SW4 = SW_PB_4P
TP1-TP4 = TEST_POINT
TP5-TP7 TP14 = T POINT R: Tolerance: TOLERANCE; User Part Number: 510-75618
TP10 = TEST POINT L
TP11-TP13 = TestLoop
U1 = LD1117AS18
U2 = RCLAMP1654P_NEW
U3 = NCP692_6P
U4 = XC6203E202MR-G_SOT23_3
U9 = TJA1044GT
U11 U22 U24 = 74AVC4TD245BQ_DHVQFN16
U12 = FXOS8700CQ_QFN_16P
U16 = LPC432_BGA_100P
U17 = 74AVC2T45_8P
U18 = NX3DV2567GU_XQFN_16P
U19-U21 U25 U26 = 74LVCH1T45_6P
U23 = 74AUP1G07GW
U28 = LPC55S06JBD_HTQFP64
U29 = MX25R6435FM2IL0
Y1 = XTAL
Y2 = XTAL_13
Y3 = CRYSTAL

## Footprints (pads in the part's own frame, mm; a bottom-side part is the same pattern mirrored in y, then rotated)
0402_CC
  rect 0.457x0.508 smd: 1(-0.375,0) 2(0.375,0)
CC0402_25
  round 0.635 smd: 1(-0.508,0) 2(0.508,0)
CC0402_TOL0P2
  rect 0.457x0.61 smd: 1(-0.475,0) 2(0.475,0)
CC0402_TOL0P15
  rect 0.457x0.61 smd: 1(-0.475,0) 2(0.475,0)
CC0603_OV
  oval 0.889x1.143 smd: 1(-0.762,0) 2(0.762,0)
CON9_MICROB_USB_SHELL_TH
  rect 1.778x1.88 smd: (-1.139,0) (1.139,0)
  rect 0.406x1.346 smd: 1(-1.3,2.677) 2(-0.65,2.677) 3(0,2.677) 4(0.65,2.677) 5(1.3,2.677)
  oval 1.041x1.245 hole 0.66x0.838: 6(-2.425,3) 7(2.425,3)
  custom 0.475x0.475 hole 1.499x0.813: 8(-3.65,0) 9(3.65,0)
CON_1X8_SKT_2P54_TH
  rect 1.702x1.702 hole 1.016: 1(0,0)
  round 1.702 hole 1.016: 2(0,-2.54) 3(0,-5.08) 4(0,-7.62) 5(0,-10.16) 6(0,-12.7) 7(0,-15.24) 8(0,-17.78)
CON_2X6_SKT_100_TH
  rect 1.651x1.651 hole 1.016: 1(0,0)
  round 1.651 hole 1.016: 2(0,-2.54) 3(2.54,0) 4(2.54,-2.54) 5(5.08,0) 6(5.08,-2.54) 7(7.62,0) 8(7.62,-2.54) 9(10.16,0) 10(10.16,-2.54) 11(12.7,0) 12(12.7,-2.54)
CON_DB9S_TH_RA_318
  rect 1.829x1.829 hole 1.194: 1(-11.074,0)
  round 1.829 hole 1.194: 2(-8.306,0) 3(-5.537,0) 4(-2.769,0) 5(0,0) 6(-9.69,-2.845) 7(-6.921,-2.845) 8(-4.153,-2.845) 9(-1.384,-2.845)
  round 3.962 hole 3.2: M1(6.96,-1.422) M2(-18.034,-1.422)
CON_SKT2X10_TH
  rect 1.651x1.651 hole 1.016: 1(0,0)
  round 1.651 hole 1.016: 2(-2.54,0) 3(0,-2.54) 4(-2.54,-2.54) 5(0,-5.08) 6(-2.54,-5.08) 7(0,-7.62) 8(-2.54,-7.62) 9(0,-10.16) 10(-2.54,-10.16) 11(0,-12.7) 12(-2.54,-12.7) 13(0,-15.24) 14(-2.54,-15.24) 15(0,-17.78) 16(-2.54,-17.78) 17(0,-20.32) 18(-2.54,-20.32) 19(0,-22.86) 20(-2.54,-22.86)
DFN6_0P95_3X3
  rect 0.889x0.457 smd: 1(-1.469,0.95) 2(-1.469,0) 3(-1.469,-0.95) 4(1.469,-0.95) 5(1.469,0) 6(1.469,0.95)
  rect 1.676x2.591 smd: 7(0,0)
DFN1010N-6_0P35_1P15X1P05
  rect 0.356x0.178 smd: 1(-0.433,0.35) 2(-0.433,0) 3(-0.433,-0.35) 4(0.433,-0.35) 5(0.433,0) 6(0.433,0.35)
  rect 0.254x0.406 smd: 7(0,0.275) 8(0,-0.275)
DHVQFN16_0P5_3P6X2P6
  rect 0.305x0.838 smd: 1(-0.25,1.719) 8(-0.25,-1.719) 9(0.25,-1.719) 16(0.25,1.719)
  rect 0.838x0.305 smd: 2(-1.219,1.25) 3(-1.219,0.75) 4(-1.219,0.25) 5(-1.219,-0.25) 6(-1.219,-0.75) 7(-1.219,-1.25) 10(1.219,-1.25) 11(1.219,-0.75) 12(1.219,-0.25) 13(1.219,0.25) 14(1.219,0.75) 15(1.219,1.25)
  rect 1.143x2.159 smd: 17(0,0)
FBGA100_0P8_9X9
  round 0.406 smd: A1(-3.6,3.6) A2(-2.8,3.6) A3(-2,3.6) A4(-1.2,3.6) A5(-0.4,3.6) A6(0.4,3.6) A7(1.2,3.6) A8(2,3.6) A9(2.8,3.6) A10(3.6,3.6) B1(-3.6,2.8) B2(-2.8,2.8) B3(-2,2.8) B4(-1.2,2.8) B5(-0.4,2.8) B6(0.4,2.8) B7(1.2,2.8) B8(2,2.8) B9(2.8,2.8) B10(3.6,2.8) C1(-3.6,2) C2(-2.8,2) C3(-2,2) C4(-1.2,2) C5(-0.4,2) C6(0.4,2) C7(1.2,2) C8(2,2) C9(2.8,2) C10(3.6,2) D1(-3.6,1.2) D2(-2.8,1.2) D3(-2,1.2) D4(-1.2,1.2) D5(-0.4,1.2) D6(0.4,1.2) D7(1.2,1.2) D8(2,1.2) D9(2.8,1.2) D10(3.6,1.2) E1(-3.6,0.4) E2(-2.8,0.4) E3(-2,0.4) E4(-1.2,0.4) E5(-0.4,0.4) E6(0.4,0.4) E7(1.2,0.4) E8(2,0.4) E9(2.8,0.4) E10(3.6,0.4) F1(-3.6,-0.4) F2(-2.8,-0.4) F3(-2,-0.4) F4(-1.2,-0.4) F5(-0.4,-0.4) F6(0.4,-0.4) F7(1.2,-0.4) F8(2,-0.4) F9(2.8,-0.4) F10(3.6,-0.4) G1(-3.6,-1.2) G2(-2.8,-1.2) G3(-2,-1.2) G4(-1.2,-1.2) G5(-0.4,-1.2) G6(0.4,-1.2) G7(1.2,-1.2) G8(2,-1.2) G9(2.8,-1.2) G10(3.6,-1.2) H1(-3.6,-2) H2(-2.8,-2) H3(-2,-2) H4(-1.2,-2) H5(-0.4,-2) H6(0.4,-2) H7(1.2,-2) H8(2,-2) H9(2.8,-2) H10(3.6,-2) J1(-3.6,-2.8) J2(-2.8,-2.8) J3(-2,-2.8) J4(-1.2,-2.8) J5(-0.4,-2.8) J6(0.4,-2.8) J7(1.2,-2.8) J8(2,-2.8) J9(2.8,-2.8) J10(3.6,-2.8) K1(-3.6,-3.6) K2(-2.8,-3.6) K3(-2,-3.6) K4(-1.2,-3.6) K5(-0.4,-3.6) K6(0.4,-3.6) K7(1.2,-3.6) K8(2,-3.6) K9(2.8,-3.6) K10(3.6,-3.6)
HDR1X4_2P54_TH
  rect 1.727x1.727 hole 1.092: 1(0,0)
  round 1.727 hole 1.092: 2(0,-2.54) 3(0,-5.08) 4(0,-7.62)
HDR102
  rect 1.524x1.524 hole 1.016: 1(0,0)
  round 1.524 hole 1.016: 2(0,-2.54)
HDR103
  rect 1.524x1.524 hole 1.016: 1(0,0)
  round 1.524 hole 1.016: 2(0,-2.54) 3(0,-5.08)
HDR205_50_TH
  rect 1.016x1.016 hole 0.66: 1(0,0)
  round 1.016 hole 0.66: 2(0,1.27) 3(1.27,0) 4(1.27,1.27) 5(2.54,0) 6(2.54,1.27) 7(3.81,0) 8(3.81,1.27) 9(5.08,0) 10(5.08,1.27)
HDR_1X2
  rect 1.524x1.524 hole 1.016: 1(0,0)
  round 1.524 hole 1.016: 2(0,-2.54)
IND2_2722
  rect 0.813x2.007 smd: 1(-1,0) 2(1,0)
IND_1P8X1MM_SM
  rect 0.991x0.711 smd: 1(-0.845,0) 2(0.845,0)
IND_1608
  rect 0.61x0.813 smd: 1(-0.7,0) 2(0.7,0)
LED4_0P4_3P4X3MM
  rect 3.302x2.489 smd: 1(1.856,1.495) 2(-1.856,1.495) 3(-1.856,-1.495) 4(1.856,-1.495)
LED_0603
  rect 0.838x0.787 smd: A(-0.775,0) C(0.775,0)
MSOP_8P_0P65_3X3MM
  rect 0.432x0.889 smd: 1(-0.975,-2.17) 2(-0.325,-2.17) 3(0.325,-2.17) 4(0.975,-2.17) 5(0.975,2.17) 6(0.325,2.17) 7(-0.325,2.17) 8(-0.975,2.17)
PQFN16_0P4_2P65X1P85
  rect 0.203x0.762 smd: 1(-0.6,-0.724)
  rect 0.203x0.66 smd: 2(-0.2,-0.775) 3(0.2,-0.775) 4(0.6,-0.775) 9(0.6,0.775) 10(0.2,0.775) 11(-0.2,0.775) 12(-0.6,0.775)
  rect 0.66x0.203 smd: 5(1.21,-0.6) 6(1.21,-0.2) 7(1.21,0.2) 8(1.21,0.6) 13(-1.21,0.6) 14(-1.21,0.2) 15(-1.21,-0.2) 16(-1.21,-0.6)
QFN5X3_0P5_3X3
  rect 0.813x0.305 smd: 1(-1.275,1) 2(-1.275,0.5) 3(-1.275,0) 4(-1.275,-0.5) 5(-1.275,-1) 9(1.275,-1) 10(1.275,-0.5) 11(1.275,0) 12(1.275,0.5) 13(1.275,1)
  rect 0.305x0.813 smd: 6(-0.5,-1.275) 7(0,-1.275) 8(0.5,-1.275) 14(0.5,1.275) 15(0,1.275) 16(-0.5,1.275)
RC0402_25
  round 0.635 smd: 1(-0.508,0) 2(0.508,0)
RC0603_OV
  oval 0.889x1.143 smd: 1(-0.762,0) 2(0.762,0)
SC70-5
  rect 0.406x0.813 smd: 1(-0.65,-1.079) 2(0,-1.079) 3(0.65,-1.079) 4(0.65,1.079) 5(-0.65,1.079)
SKT2X6_100_TH_RA
  rect 1.651x1.651 hole 1.016: 1(0,0)
  round 1.651 hole 1.016: 2(2.54,0) 3(0,-2.54) 4(2.54,-2.54) 5(0,-5.08) 6(2.54,-5.08) 7(0,-7.62) 8(2.54,-7.62) 9(0,-10.16) 10(2.54,-10.16) 11(0,-12.7) 12(2.54,-12.7)
SKT_QFP64_0P5_22P25SQ_MM
  round 0.254 hole 1.702 unplated: (-8.863,8.863) (-8.863,-8.863) (8.863,8.863) (8.863,-8.863)
  round 0.254 hole 0.838 unplated: (-8.863,-3.783) (8.863,6.323)
  rect 1.549x0.254 smd: 1(-5.35,3.75) 2(-5.35,3.25) 3(-5.35,2.75) 4(-5.35,2.25) 5(-5.35,1.75) 6(-5.35,1.25) 7(-5.35,0.75) 8(-5.35,0.25) 9(-5.35,-0.25) 10(-5.35,-0.75) 11(-5.35,-1.25) 12(-5.35,-1.75) 13(-5.35,-2.25) 14(-5.35,-2.75) 15(-5.35,-3.25) 16(-5.35,-3.75) 33(5.85,-3.75) 34(5.85,-3.25) 35(5.85,-2.75) 36(5.85,-2.25) 37(5.85,-1.75) 38(5.85,-1.25) 39(5.85,-0.75) 40(5.85,-0.25) 41(5.85,0.25) 42(5.85,0.75) 43(5.85,1.25) 44(5.85,1.75) 45(5.85,2.25) 46(5.85,2.75) 47(5.85,3.25) 48(5.85,3.75)
  rect 0.254x1.549 smd: 17(-3.5,-5.6) 18(-3,-5.6) 19(-2.5,-5.6) 20(-2,-5.6) 21(-1.5,-5.6) 22(-1,-5.6) 23(-0.5,-5.6) 24(0,-5.6) 25(0.5,-5.6) 26(1,-5.6) 27(1.5,-5.6) 28(2,-5.6) 29(2.5,-5.6) 30(3,-5.6) 31(3.5,-5.6) 32(4,-5.6) 49(4,5.6) 50(3.5,5.6) 51(3,5.6) 52(2.5,5.6) 53(2,5.6) 54(1.5,5.6) 55(1,5.6) 56(0.5,5.6) 57(0,5.6) 58(-0.5,5.6) 59(-1,5.6) 60(-1.5,5.6) 61(-2,5.6) 62(-2.5,5.6) 63(-3,5.6) 64(-3.5,5.6)
  rect 2.921x2.921 smd: 65(0.25,0)
SLP1616P6
  rect 0.305x0.635 smd: 1(-0.5,-0.76) 2(0,-0.76) 3(0.5,-0.76) 4(0.5,0.76) 5(0,0.76) 6(-0.5,0.76)
  rect 1.295x0.457 smd: 7(0,0)
SO8-25X75-200
  oval 0.635x1.905 smd: 1(-1.905,-3.67) 2(-0.635,-3.67) 3(0.635,-3.67) 4(1.905,-3.67) 5(1.905,3.67) 6(0.635,3.67) 7(-0.635,3.67) 8(-1.905,3.67)
SO8_1P27_4X5
  rect 1.6x0.61 smd: 1(-2.7,1.905) 2(-2.7,0.635) 3(-2.7,-0.635) 4(-2.7,-1.905) 5(2.7,-1.905) 6(2.7,-0.635) 7(2.7,0.635) 8(2.7,1.905)
SOD123LF
  rect 1.219x1.27 smd: A(1.549,0) C(-1.549,0)
SOD123W
  rect 1.219x1.219 smd: A(1.4,0) C(-1.4,0)
SOD523
  rect 0.61x0.813 smd: A(0.85,0) C(-0.85,0)
SOT23_A
  rect 0.787x0.889 smd: 1(-0.94,-1.003) 2(0.94,-1.003) 3(0,1.003)
SOT223
  rect 1.194x2.21 smd: 1(-2.3,-3.1) 2(0,-3.1) 3(2.3,-3.1)
  rect 3.734x2.21 smd: 4(0,3.1)
SOT-23
  rect 1.016x1.397 smd: 1(-0.95,-1.1) 2(0.95,-1.1) 3(0,1.1)
SOT-363_0P65_SMT
  rect 0.762x0.381 smd: 1(-1.085,0.65) 2(-1.085,0) 3(-1.085,-0.65) 4(1.085,-0.65) 5(1.085,0) 6(1.085,0.65)
SPACER_139T
  round 5.588 hole 3.531: 1(0,0)
SW4_4P2X2P8_SM
  rect 0.914x1.016 smd: 1(-2.05,0.8) 2(2.05,0.8) 3(-2.05,-0.8) 4(2.05,-0.8)
TESTPOINT_35MIL
  round 0.889 smd: 1(0,0)
TP_2P7X4P7MM
  rect 2.692x4.699 smd: 1(0,0)
TPAD_020
  round 0.508 smd: 1(0,0)
TPAD_050
  round 1.27 smd: 1(0,0)
TQFP64_0P5_10X10_EP_3P31
  rect 1.499x0.279 smd: 1(-5.75,3.75) 2(-5.75,3.25) 3(-5.75,2.75) 4(-5.75,2.25) 5(-5.75,1.75) 6(-5.75,1.25) 7(-5.75,0.75) 8(-5.75,0.25) 9(-5.75,-0.25) 10(-5.75,-0.75) 11(-5.75,-1.25) 12(-5.75,-1.75) 13(-5.75,-2.25) 14(-5.75,-2.75) 15(-5.75,-3.25) 16(-5.75,-3.75) 33(5.75,-3.75) 34(5.75,-3.25) 35(5.75,-2.75) 36(5.75,-2.25) 37(5.75,-1.75) 38(5.75,-1.25) 39(5.75,-0.75) 40(5.75,-0.25) 41(5.75,0.25) 42(5.75,0.75) 43(5.75,1.25) 44(5.75,1.75) 45(5.75,2.25) 46(5.75,2.75) 47(5.75,3.25) 48(5.75,3.75)
  rect 0.279x1.499 smd: 17(-3.75,-5.75) 18(-3.25,-5.75) 19(-2.75,-5.75) 20(-2.25,-5.75) 21(-1.75,-5.75) 22(-1.25,-5.75) 23(-0.75,-5.75) 24(-0.25,-5.75) 25(0.25,-5.75) 26(0.75,-5.75) 27(1.25,-5.75) 28(1.75,-5.75) 29(2.25,-5.75) 30(2.75,-5.75) 31(3.25,-5.75) 32(3.75,-5.75) 49(3.75,5.75) 50(3.25,5.75) 51(2.75,5.75) 52(2.25,5.75) 53(1.75,5.75) 54(1.25,5.75) 55(0.75,5.75) 56(0.25,5.75) 57(-0.25,5.75) 58(-0.75,5.75) 59(-1.25,5.75) 60(-1.75,5.75) 61(-2.25,5.75) 62(-2.75,5.75) 63(-3.25,5.75) 64(-3.75,5.75)
  rect 3.2x3.2 smd: 65(0,0)
unnamed#2
  round 1.524 smd: (0,0)
XTAL2-3P2X1P5-SM
  rect 1.092x1.905 smd: 1(-1.25,0) 2(1.25,0)
XTAL_4_3P3X2P6MM
  rect 1.397x1.194 smd: 1(-1.1,-0.85) 2(1.1,-0.85) 3(1.1,0.85) 4(-1.1,0.85)
XTL2_11P6X4P85_SM
  rect 5.588x2.032 smd: 1(-4.75,0) 2(4.75,0)

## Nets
GND: C1.2 C2.2 C3.2 C4.2 C5.2 C6.2 C7.2 C8.2 C10.2 C11.2 C12.2 C18.2 C19.2 C22.2 C23.2 C24.2 C25.2 C27.2 C28.2 C29.2 C30.2 C31.2 C32.2 C33.2 C34.2 C55.2 C56.2 C57.2 C58.2 C59.2 C69.2 C70.2 C71.2 C72.2 C73.2 C74.2 C75.2 C76.2 C77.2 C78.2 C79.2 C80.2 C81.2 C82.2 C83.2 C84.2 C85.2 C86.2 C87.2 C88.2 C89.2 C90.2 C91.2 C92.2 C93.2 C94.2 C95.2 C96.2 C97.2 C98.2 C442.2 C443.2 C444.2 C445.2 C446.2 C447.2 C448.2 C449.2 C450.2 C451.2 C457.2 C458.2 C459.2 C460.2 C461.2 C462.2 C463.2 C464.2 C465.2 C466.2 C467.2 C468.2 D3.3(CC) D8.C(CATHODE) D10.A D11.2 D12.A J1.5 J3.3 J7.8 J8.8 J9.8 J10.15 J10.17 J11.4 J16.3 J16.5 J17.3 J17.5 J18.9 J18.10 J19.3 J32.11 J32.30 J32.65 JP4.2 JP6.2 JS1.2 JS3.2 L2.2 L7.2 Q4.1 Q4.4(SOURCE2) Q5.1 Q5.4(SOURCE2) R28.2 R29.2 R39.2 R40.2 R41.2 R95.2 R99.1 R101.1 R102.2 R107.2 R108.2 R109.2 R110.2 R114.2 R115.2 R120.2 R121.2 R124.2 R125.2 R128.2 R134.2 R146.2 R159.2 R160.2 R163.2 R165.2 SS1.1(NC_1) SS2.1(NC_1) SS3.1(NC_1) SS4.1(NC_1) SW1.3 SW1.4 SW2.3 SW2.4 SW3.3 SW3.4 SW4.3 SW4.4 TP1.1 TP2.1 TP3.1 TP4.1 TP7.1(TP) U1.1 U2.7 U3.2 U3.7 U4.1(VSS) U9.2 U11.7 U11.8 U11.10 U11.15 U11.17 U12.3 U12.5 U12.12 U12.13 U16.C2 U16.C8 U16.D3 U16.D4 U16.D5 U16.F2 U16.G8 U16.J3 U16.J6 U17.4 U18.5 U18.6 U18.9 U19.2 U20.2 U21.2 U22.8 U22.10 U22.15 U22.17 U23.3 U24.8 U24.10 U24.17 U25.2 U26.2 U28.11 U28.30 U28.65 U29.4 Y2.2 Y2.4
VCC_2V0: C12.1 JP1.3 TP13.1(PIN1) U4.2
VCC_3V3: C7.1 C22.1 C27.1 C28.1 D4.2 JP1.1 R20.1 R37.1 R152.1 R153.1 R158.1 TP12.1(PIN1) U3.4 U3.5(SNS) U11.1 U11.2 U12.14
VCC_3V3_2V0: C8.1 C24.1 C29.1 C58.1 C59.1 C84.1 C93.1 C95.1 C97.1 C442.1 C444.1 C466.1 D9.A J10.11 J18.11 J18.12(B6) JP1.2 JP8.1 JP20.1 JP21.1 JP22.1 JS1.1 R19.1 R32.1 R33.1 R34.1 R35.1 R42.2 R43.1 R44.1 R45.1 R61.2 R62.1 R65.1 R74.1 R75.1 R117.2 R147.1 R148.1 R149.1 U11.16(VCCB) U12.1(VDDIO) U18.14(VCC) U22.16(VCCB) U24.16(VCCB) U25.1 U26.1 U29.8
VCC_IF_LINK: C83.1 C86.1 C87.1 C89.1 C91.1 J17.1 JP8.2 R116.1 R122.1 R126.1 U17.8(VCCB) U19.6(VCCB) U20.6(VCCB) U21.6(VCCB)
ACC_FC0_I2C_SCL: R77.2 U12.4
ACC_FC0_I2C_SDA: R84.2 U12.6
ACC_INT_EXP_P1_23: J9.5 J32.27 R36.1 U28.27
ARD_ADC0_0_P: J12.10 J13.3 J13.8 J32.12 JP4.3 U28.12
ARD_BTN_USR_P1_9: J13.2 J32.3 R47.2 U28.3(PIO1_9/ADC0_12/FC1_SCK/CTIMER_I)
ARD_CMP0_IN_A: J9.1 J11.2 J13.7 J32.36 U28.36
ARD_INT_P0_15: J12.12 J32.14 U28.14
ARD_LEDB_PWM: J12.8 J32.51 R161.1 U28.51
ARD_LEDG_PWM: J12.4 J32.38 R162.1 U28.38
ARD_LEDR_PWM: J9.2 J9.13 J12.5 J32.49 R164.1 U28.49
ARD_MIK_ADC0_8_N: J7.1 J13.1 J32.7 JP4.1 U28.7
ARD_MIK_FC0_I2C_SCL: J8.5 R80.2
ARD_MIK_FC0_I2C_SDA: J8.6 R88.2
ARD_MIK_FC1_USART_RXD: J8.3 J12.16 J13.4 J32.25 U28.25
ARD_MIK_FC1_USART_TXD: J8.4 J12.14 J13.6 J32.62 U28.62
ARD_MIK_HSSPI_MISO: J7.5 J9.12 JP25.1
ARD_MIK_HSSPI_MOSI: J7.6 J9.14 J32.40 R138.1 U24.11 U28.40
ARD_MIK_HSSPI_SCK: J7.4 J9.10 JP26.1
ARD_MIK_HSSPI_SSEL1: J7.3 J9.16 J32.39 R139.1 U24.14 U28.39
ARD_MIK_P1_5: J8.1 J12.20 J32.22 U28.22
BRG_I2C0_SCL: JS4.1 R91.2 U16.D6
BRG_I2C0_SDA: JS5.1 R92.2 U16.E6
BRG_INTR_ISP: R132.2 U16.J5
BRG_INTR_ISP_DIR: R134.1 U16.J7 U22.7
BRG_ISP_CTRL: U16.A9 U23.2
BRG_RESET_TXEN: R128.1 U16.G9 U21.5
BRG_SPI1_MISO: U16.J1 U24.5
BRG_SPI1_MOSI: U16.J2 U24.6
BRG_SPI1_SCLK: U16.K9 U24.4
BRG_SPI1_SSEL: U16.K10 U24.3
BRG_TCK_SWCLK: U16.H10 U17.2
BRG_TDI: U16.J10 U17.3
BRG_TDO_SWO: U16.J8 U19.3
BRG_TMS_SWDIO: U16.K4 U20.3
BRG_TMS_SWDIO_TXEN: R124.1 U16.J4 U20.5
BRG_TRST_SWDRST: U16.D10 U21.3
BRG_UART0_RXD: U16.G10 U22.3
BRG_UART0_TXD: R129.2 U16.G7 U22.4
CAN__HSSPI_ISP_PIO1_2: J32.41 JP26.2 R143.1 U24.13 U28.41
CAN__HSSPI_ISP_PIO1_3: J32.42 JP25.2 R140.1 U24.12 U28.42
CAN_RXD: JP25.3 U25.3
CAN_TXD: JP26.3 U26.3
CANH: D3.1 J19.7 JP23.2 U9.7
CANL: D3.2 J19.2 JP24.2 U9.6
EXP_CMP0_IN_B: J11.1 J13.5 J32.37 U28.37
EXP_CMP0_OUT: J9.3 J11.3 J32.2 U28.2
EXP_ISP_P1_29: J10.20 J12.11 J32.53 R137.2 U28.53
FB: C18.1 C19.1 C461.1 J32.24 J32.29 L11.2 U28.24 U28.29
FC0_I2C_SCL: J10.3 J32.52 R74.2 R77.1 R80.1 U28.52
FC0_I2C_SDA: J9.18 J32.45 R75.2 R84.1 R88.1 U28.45
FC0_USART_RXD: J32.61 R24.2 R130.2 U28.61
FC0_USART_TXD: J10.18 J32.63 R26.2 R131.2 U28.63
FC1_I2C_SCL: J12.19 J13.11 J13.12(B6) J32.47 JS4.2 R144.2 R148.2 U28.47
FC1_I2C_SDA: J13.9 J13.10 J32.46 JS5.2 R145.2 R149.2 U28.46
FC3_MISO: JP27.1 U29.2
FC3_MOSI: JP28.1 U29.5
FC3_SCK: JP30.1 U29.6
FC3_SSEL0: JP29.1 U29.1
FL_2V5: C4.1 C5.1 C69.1 C70.1 C71.1 C72.1 C81.1 C82.1 C85.1 C88.1 C90.1 C92.1 C94.1 C96.1 J16.1 JP9.1 L10.1 R91.1 R92.1 R96.1 R97.1 R98.1 R100.1 R105.1 R113.2 R129.1 R151.1 TP11.1(PIN1) U1.2(VOUT) U16.B2 U16.C5 U16.F10 U16.K5 U17.1 U19.1 U20.1 U21.1 U22.1 U22.2 U23.5 U24.1 U24.2 U24.7 U24.15
FL_BOOT0_LED: R105.2 R106.1 U16.K2
FL_BOOT1: R99.2 U16.K1
FL_BOOT2: R100.2 U16.C6
FL_BOOT3: R101.2 U16.B10
FL_ISP_BOOT: JP6.1 U16.C10
FL_JTAG_CLK_SWD_CLK: J16.4 R102.1 U16.H2
FL_JTAG_TDI: J16.8 U16.G3
FL_JTAG_TDO_SWD_SWO: J16.6 U16.H3
FL_JTAG_TMS_SWD_IO: J16.2 U16.C4
FL_JTAG_TRST: R104.2 U16.B4
FL_RST#: J16.10(B5) R98.2 U16.B6
FL_USB0_DM: R1.2 U16.E2
FL_USB0_DP: R2.2 U16.E1
FL_USB0_ID: R3.2 R93.2
FL_USB_5V0: C2.1 C3.1 D1.A L1.2 R94.2 TP14.1(TP) U1.3
IF_DETECT: D10.C J17.9 R103.1 R125.1
IF_TCK_SWDCLK: D11.5 J17.4 JP13.2 U18.3
IF_TDI: D11.3 J17.8 JP14.1
IF_TDO_SWO: D11.4 J17.6 JP15.2 U18.11
IF_TMS_SWDIO: D11.6(K5) J17.2 JP16.2 U18.7
IF_TRST_SWDRST: D11.1 J17.10(B5) JP17.2 U18.15
ISP_P1_19: J32.26 R142.2 U28.26
LPC_VDDA: C460.1 J32.9(IO9) R166.2 U28.9
LX: J32.31 L11.1 U28.31
MCU_VBAT: C457.1 C458.1 C459.1 C467.1 J32.32 J32.33 JP22.2 U28.32 U28.33
MCU_VDD: C446.1 C447.1 C448.1 C449.1 C450.1 C451.1 J32.8 J32.16 J32.28 J32.43 J32.56 JP20.2 U28.8 U28.16 U28.28 U28.43 U28.56
MCU_VDDA: JP21.2 R166.1
MIK_EXP_BTN_WK: J8.2 J10.1 J12.15 J32.44 R46.2 U28.44
N4M_ISP_MODE: D12.C J9.7 J17.7 J32.58 R133.2 R135.2 R136.2 R150.2 U28.58
N4M_RESET#: J7.2 J10.9 J10.10 J32.23 R48.2 U18.16 U28.23
N4M_SWDCLK: J9.19 J10.8 J32.6 R115.1 U18.4 U28.6
N4M_SWDIO: J9.17 J10.6 J32.5 U18.8 U28.5
N4M_SWO: J9.15 J9.20 J32.13 U18.12 U28.13
P0_7: J10.4 J32.1 U28.1
P0_8: J10.5 J32.17 U28.17
P0_19: J9.11 J12.6 J32.60 U28.60
P0_20: J9.4 J9.9 J12.9 J32.48 U28.48
P0_27: J12.17 J32.18 U28.18
P0_31: J10.2 J32.15 U28.15
P1_0: J12.7 J32.4 U28.4
P1_4: J12.18 J32.64 U28.64
P1_21: J12.13 J32.21 U28.21 U29.7
P1_25: J12.3 J32.50 U28.50 U29.3(W\P/SIO2)
SPI_FLASH_PIO0_2: J12.2 J32.54 JP27.2 U28.54
SPI_FLASH_PIO0_3: J12.1 J32.55 JP28.2 U28.55
SPI_FLASH_PIO0_4: J10.14 J32.57 JP29.2 U28.57
SPI_FLASH_PIO0_6: J10.16 J32.59 JP30.2 U28.59
SWD_SW_SEL: R119.2 U16.G5
SYS_5V0: C6.1 C10.1 C11.1 C23.1 C57.1 C443.1 C445.1 D1.C J10.13 R60.1 R154.1 TP6.1(TP) U3.1 U3.3 U3.6 U4.3 U9.3(VCC) U25.6(VCCB) U26.6(VCCB)
TAB: U1.4
UART_SPI_EN#: JP9.2 R146.1 U22.9 U24.9
VREFP: C468.1 J32.10 R65.2 U28.10
XTAL1: C79.1 U16.B1 Y1.2
XTAL2: C80.1 U16.C1 Y1.1
XTAL32K_N: C465.1 J32.35 U28.35 Y3.1
XTAL32K_P: C464.1 J32.34 U28.34 Y3.2
XTAL32M_N: C463.1 J32.19 U28.19 Y2.1
XTAL32M_P: C462.1 J32.20 U28.20 Y2.3
N00831: J1.6 J1.7 J1.8 J1.9 L2.1
N00949: C1.1 J1.1(VBUS) L1.1 U2.6(VBUS)
N00991: J1.2 R1.1 U2.1
N01033: J1.3 R2.1 U2.2
N01077: J1.4 R3.1 TP5.1(TP) U2.3
N10980: C73.1 C74.1 C75.1 L10.2 U16.E4 U16.E5 U16.F4
N11774: R103.2 U16.A10
N11936: R107.1 U16.J9
N11954: R94.1 U16.E3
N11988: R108.1 U16.F9
N12006: R93.1 U16.F1
N12034: R109.1 U16.F8
N12048: R95.1 U16.F3
N12060: R110.1 U16.C9
N12096: C76.1 C77.1 C78.1 R151.2 R152.2 U16.D1 U16.D2
N12268: R96.2 U16.A6
N12370: R97.2 U16.A4
N12878: D8.A R106.2
N26173: J16.9 R104.1
N35294: R111.1 U17.7
N35350: R112.1 U17.6
N35394: R113.1 U17.5
N35580: D9.C JP8.3
N35730: R116.2 R118.1 U19.4
N36212: R122.2 R123.1 U20.4
N36294: JP7.1 R117.1 R119.1 U18.2
N36440: JP7.2 R121.1
N36658: R126.2 R127.1 U21.4
N37764: R120.1 U19.5
N44150: R114.1 U18.1
N59397: R132.1 U22.6
N60020: R133.1 U22.11
N63149: J18.1 R139.2
N63153: R136.1 R137.1 R141.2
N63221: J18.3 R138.2
N63225: J18.4 R142.1
N63293: J18.5 R140.2
N63337: J18.7 R143.2
N67918: R135.1 U23.4(Y)
N70850: C98.1 JS3.1 R147.2 R150.1 SW4.1 SW4.2
N73960: J18.6 R144.1
N73966: J18.8 R145.1
N74033: J18.2 R141.1
N75462: J3.1 R20.2 R23.1
N75944: JP12.2 R28.1 U11.9
N76496: J3.2 R25.1
N76500: R25.2 U11.4
N76504: R23.2 U11.3
N76612: R24.1 U11.14
N76618: R26.1 U11.13
N76712: R130.1 U22.14
N76718: R131.1 U22.13
N79087: C32.1 R43.2 R46.1 SW1.1 SW1.2
N79544: C33.1 R44.2 R48.1 SW2.1 SW2.2
N80467: C34.1 R45.2 R47.1 SW3.1 SW3.2
N84474: Q4.6 Q4.7 R30.2
N84482: D4.3 R30.1
N84508: Q4.3 Q4.8 R31.2
N84516: D4.4(CATHODE3) R31.1
N84524: D4.1 R38.1
N84614: Q4.2 R160.1 R161.2
N84618: Q4.5 R162.2 R163.1
N84662: D5.A R37.2
N84682: Q5.6 Q5.7 R38.2
N84732: D5.C(CATHODE) Q5.3 Q5.8
N84806: Q5.2 R164.2 R165.1
N105040: R29.1 U9.8
N105919: J19.M1 J19.M2 L7.1
N108963: R32.2 TP10.1(TP) U12.9
N108967: R33.2 R36.2 U12.11
N109097: R34.2 R39.1 U12.7
N109101: R35.2 R40.1 U12.10
N109113: C30.1 U12.8
N109175: R41.1 U12.16
N109231: C31.1 U12.2
N110947: Q5.5 R42.1
N112208: U9.1 U26.4
N112220: U9.4 U25.4
N115095: C55.1 J7.7 R153.2
N115099: C56.1 J8.7 R154.2
N115914: J10.7 R62.2
N116004: J10.19 R60.2
N116129: J9.6 R61.1
N339341: JP12.1 R158.2
N346834: JP13.1 R111.2
N346895: JP14.2 R112.2
N346946: JP15.1 R118.2
N347023: JP16.1 R123.2
N347072: JP17.1 R127.2
N348380: R159.1 U25.5
N350950: R19.2 U26.5
N1378690: C25.1 R21.2 R27.2
N1379290: JP23.1 R21.1
N1379309: JP24.1 R27.1

Pads without a net: J10 12; J16 7; J19 1 4 5 6 8 9; U2 4 5; U9 5; U11 5 6 11 12; U12 15; U16 A1 A2 A3 A5 A7 A8 B3 B5 B7 B8 B9 C3 C7 D7 D8 D9 E7 E8 E9 E10 F5 F6 F7 G1 G2 G4 G6 H1 H4 H5 H6 H7 H8 H9 K3 K6 K7 K8; U18 10 13; U22 5 12; U23 1

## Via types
v1: diameter 0.457, hole 0.203, TOP to BOTTOM, 346 vias
v2: diameter 0.508, hole 0.254, TOP to BOTTOM, 230 vias

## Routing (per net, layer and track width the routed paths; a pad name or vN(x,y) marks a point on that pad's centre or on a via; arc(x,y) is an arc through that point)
GND: length 607.8
  TOP w0.254: SW3.4 102.15,21.25 ; SW3.4 101.45,21.9 ; SW3.4 100.75,21.25 ; 101.6,62.48 R39.2 ; 23.06,49.38 C92.2 23.06,50.4 ; TP2.1 103.9,55.37 ; TP2.1 102.36,52.83 ; TP2.1 100.82,55.37 ; TP2.1 102.36,57.92 ; C58.2 80.64,47.76 ; 44.7,90.04 R159.2 44.7,89.02 ; v2(14.48,14.49) 14.88,14.09 U24.8 ; 6.1,34.09 C72.2 6.1,33.07 ; D10.A 54.19,80.73 ; D10.A 53.59,80.23 ; D10.A 53.59,81.23 ; D10.A 52.99,80.73 ; C90.2 24.77,76.84 ; C90.2 25.28,76.33 ; C90.2 24.25,76.33 ; C12.2 v2(18.03,76.33) ; 92.64,49.53 JS3.2 ; JS3.2 93.6,48.57 ; JS3.2 94.55,49.53 ; JS3.2 93.6,50.49 ; 53.33,33.38 Y2.4 ; Y2.4 53.33,34.97 ; Y2.4 52.44,34.17 ; 27.02,87.02 U19.2 25.87,87.02 ; 25.35,30.3 R28.2 ; R28.2 26.37,30.3 ; R28.2 25.86,29.79 ; J8.8 49.29,25.21 ; J8.8 50.34,24.17 ; J8.8 48.25,24.17 ; U22.15 26.01,48.16 25.27,47.42 U22.17 25.27,46.05 25.02,45.8 U22.8 ; U22.15 26.49,48.51 ; U22.15 27.18,48.16 v2(27.61,48.59) ; 21.41,26.19 U11.10 22.02,26.54 ; SS2.1 103.06,5.08 ; SS2.1 97.09,5.08 ; SS2.1 100.08,2.09 ; SS2.1 100.08,8.07 ; 46.74,78.62 C84.2 47.25,78.11 ; 13.59,90.79 U29.4 ; U29.4 14.1,91.94 ; U29.4 13.59,93.08 ; U29.4 13.08,91.94 ; 65.13,30.92 C461.2 64.49,31.68 ; 52.58,97.15 C23.2 51.56,97.15 ; TP1.1 103.27,93.22 ; TP1.1 101.73,90.67 ; TP1.1 100.19,93.22 ; TP1.1 101.73,95.76 ; C97.2 20.96,12.45 ; C97.2 19.94,12.45 ; C97.2 20.45,11.93 ; 14.13,69.63 U3.2 ; U3.2 C6.2 v2(12.8,69.09) ; U3.2 U3.7 15.6,68.56 ; SS3.1 5.08,110.81 ; SS3.1 8.07,107.82 ; SS3.1 2.09,107.82 ; SS3.1 5.08,104.83 ; 44.88,79.74 D11.2 ; 31.14,83.44 C87.2 31.14,82.42 ; 98.76,75.08 R160.2 ; 15.06,25.78 C80.2 ; C80.2 15.06,26.8 ; C80.2 15.57,26.29 ; 91.91,9.4 J11.4 ; J11.4 94.02,9.4 ; J11.4 92.96,8.34 ; v2(27.58,45.24) 27.17,45.66 U22.10 26.49,45.32 ; SS1.1 8.07,5.08 ; SS1.1 2.09,5.08 ; SS1.1 5.08,8.07 ; SS1.1 5.08,2.09 ; 36.45,64.13 C83.2 ; C83.2 35.94,64.64 ; C83.2 36.45,65.15 ; 12.07,9.14 C95.2 11.05,9.14 ; 32.1,56.38 C4.2 32.52,55.88 ; 21.82,32.79 C74.2 21.82,33.81 ; 73.2,24.17 J7.8 71.11,24.17 ; 40.35,32.52 C57.2 ; C57.2 40.78,33.02 ; C57.2 40.35,33.52 ; 19.94,15.49 C96.2 ; C96.2 20.45,16.01 ; C96.2 20.96,15.49 ; 53.59,72.51 C89.2 ; C89.2 53.1,72.93 ; C89.2 54.09,72.93 ; C443.2 44.09,93.85 ; C443.2 43.58,93.34 ; C443.2 44.09,92.83 ; 26.51,39.14 U23.3 v2(26.11,40.08) ; 15.68,12.62 U24.10 16.02,12.01 ; v2(25.76,26.82) 25.13,26.19 U11.7 24.46,26.54 ; 40.13,73.91 R115.2 ; 3.01,26.24 C79.2 ; C79.2 3.52,25.73 ; C79.2 3.52,26.75 ; 100.75,10.19 SW1.4 ; SW1.4 101.45,9.54 ; SW1.4 101.45,10.84 ; SW1.4 102.15,10.19 ; 34.98,64.42 C3.2 35.49,64.94 ; 100.75,36.41 SW2.3 ; SW2.3 101.45,35.75 ; SW2.3 102.15,36.41 ; 2.92,16.38 C81.2 1.9,16.38 ; 64.64,92.71 C25.2 ; C25.2 65.15,92.2 ; C25.2 65.15,93.22 ; 22.21,32.16 C75.2 21.79,32.65 ; D8.C 26.42,36.36 ; D8.C 25.83,35.75 ; D8.C 25.83,36.97 ; D8.C 25.24,36.36 ; U24.8 17.02,14.09 U24.17 ; U24.8 15.55,14.44 ; 18.67,107.82 TP3.1 ; TP3.1 23.75,107.82 ; TP3.1 21.21,109.36 ; TP3.1 21.21,106.28 ; U18.9 45.79,75.16 45.97,75.34 v2(46.13,75.34) ; U11.8 v2(23.49,27.69) ; U11.8 23.49,26.08 23.24,25.83 U11.17 23.24,24.43 22.5,23.7 22.03,23.7 U11.15 ; U11.8 23.84,26.66 ; J18.10 15.08,2.79 ; J18.10 14.06,1.77 ; J18.10 14.06,3.81 ; J18.10 13.05,2.79 ; 21.82,30.53 R99.1 ; 100.75,47.47 SW4.3 ; SW4.3 102.15,47.47 ; SW4.3 101.45,46.81 ; 20.83,40.9 R107.2 20.83,39.87 ; 75.04,19.54 C55.2 76.04,19.54 ; 50.29,85.85 R121.2 50.8,86.36 ; U12.13 100.43,68.31 ; 14.06,4.31 J18.9 ; J18.9 14.06,6.35 ; J18.9 13.05,5.33 ; 47.23,93.34 U9.2 ; U9.2 48.23,93.84 ; U9.2 48.23,92.84 ; 25.85,81.52 U20.2 27,81.52 ; C464.2 76.13,39.29 ; C464.2 75.71,38.85 ; C464.2 75.71,39.74 ; v2(99.44,73.6) C27.2 99.94,72.74 ; 44.96,43.87 C460.2 ; C460.2 45.41,44.29 ; C460.2 44.51,44.29 ; 62.69,43.25 J32.30 U28.30 62.69,41.19 ; J9.8 84.86,45.72 ; J9.8 83.84,44.7 ; J9.8 85.88,44.7 ; L7.2 60.67,102.04 ; L7.2 60.07,102.54 ; L7.2 59.47,102.04 ; 10.26,28.75 C77.2 10.77,28.24 ; TP7.1 23.27,83.57 ; TP7.1 22.63,84.2 ; TP7.1 21.99,83.57 ; TP7.1 22.63,82.93 ; JP4.2 30.29,14.22 ; JP4.2 29.34,13.27 ; JP4.2 28.38,14.22 ; JP4.2 29.34,15.18 ; J3.3 29.34,23.31 ; J3.3 30.29,22.35 ; J3.3 28.38,22.35 ; J3.3 29.34,21.4 ; 21.02,59.18 JS1.2 ; JS1.2 22.93,59.18 ; JS1.2 21.97,60.14 ; JS1.2 21.97,58.23 ; 66.96,33.44 C458.2 ; C458.2 67.86,33.44 ; C458.2 67.41,33.02 ; C94.2 v2(23.37,39.4) ; C94.2 23.88,40.28 ; C94.2 22.86,40.28 ; C462.2 57.45,33.43 ; C462.2 57,33.01 ; C462.2 56.55,33.43 ; SS4.1 103.06,107.82 ; SS4.1 100.08,110.81 ; SS4.1 100.08,104.83 ; SS4.1 97.09,107.82 ; D3.3 62.06,99.04 ; D3.3 61.47,98.41 ; D3.3 60.88,99.04 ; D3.3 61.47,99.68 ; D12.A 58.51,76.02 ; D12.A 57.91,75.53 ; D12.A 57.31,76.02 ; D12.A 57.91,76.52 ; 31.15,82.06 R124.2 31.66,81.55 ; 44.17,74.02 U18.6 U18.5 43.77,74.13 43.43,73.79 v2(42.93,73.79) ; 75.71,44.54 C465.2 76.13,44.98 ; Q5.1 91.18,90.29 ; SW2.4 101.45,32.96 ; SW2.4 102.15,32.31 ; SW2.4 100.75,32.31 ; Y2.2 55.53,33.27 ; Y2.2 56.42,32.47 ; Y2.2 54.64,32.47 ; Y2.2 55.53,31.68 ; 43.69,91.44 U25.2 42.54,91.44 ; 41.66,95.64 C444.2 ; C444.2 42.17,96.15 ; C444.2 41.14,96.15 ; v2(14.61,72.52) 14.67,72.58 U4.1 13.6,73.78 v2(13.59,73.79) ; 92.05,89.03 Q5.4 ; U17.4 41.39,60.31 ; U17.4 40.98,60.95 ; U17.4 40.98,59.68 ; 5.95,58.18 L2.2 ; L2.2 7.15,58.18 ; L2.2 6.55,57.68 ; 31.8,58 U1.1 31.8,59.58 ; 65.52,33.02 C457.2 65.96,33.44 ; v2(21.08,21.97) 21.08,23.44 21.34,23.69 U11.15 ; Q4.4 99.39,78.82 ; C19.2 59.73,33.46 ; C19.2 58.84,33.46 ; C19.2 59.28,33.04 ; 41.09,91.07 C442.2 ; C442.2 42.12,91.07 ; C442.2 41.61,90.56 ; 89.97,91.57 R165.2 88.95,91.57 ; 101.45,13.64 SW1.3 ; SW1.3 102.15,14.29 ; SW1.3 100.75,14.29 ; C86.2 31.19,88.6 ; 43.3,98.42 C445.2 ; C445.2 43.81,97.91 ; C445.2 v2(43.81,99.57) ; 34.92,62.34 C2.2 ; C2.2 35.34,62.84 ; C2.2 34.92,63.34 ; 13.62,45.09 R110.2 12.6,45.09 ; 31.22,76.51 C91.2 31.22,75.49 ; 18.41,28.24 R95.2 18.93,28.75 ; 21.82,33.98 C73.2 21.82,35 ; C463.2 51.87,33.64 ; C463.2 52.31,33.22 ; C463.2 51.42,33.22 ; SW4.4 102.15,43.37 ; SW4.4 101.45,44.02 ; SW4.4 100.75,43.37 ; JP6.2 9.47,53.25 ; JP6.2 10.43,52.3 ; JP6.2 9.47,51.34 ; JP6.2 8.52,52.3 ; 44.92,19.54 C56.2 ; C56.2 45.42,19.12 ; C56.2 45.91,19.54 ; 100.75,25.35 SW3.3 ; SW3.3 101.45,24.7 ; SW3.3 102.15,25.35 ; 35.58,27.94 J10.17 ; J10.17 37.62,27.94 ; J10.17 36.6,26.92 ; 17.4,81.77 C466.2 ; C466.2 17.85,82.2 ; C466.2 16.95,82.2 ; C11.2 v2(14.1,77.47) ; 25.07,42.9 R134.2 25.07,43.92 ; TP4.1 24.77,17.16 ; TP4.1 27.31,15.62 ; TP4.1 24.77,14.08 ; TP4.1 22.22,15.62 ; 67.87,32.66 C459.2 ; C459.2 68.63,32.03 ; C459.2 69.4,32.66 ; C30.2 99.95,61.85 ; 14.84,45.09 C71.2 13.81,45.09 ; 22.32,20.47 C24.2 23.35,20.47 ; 32.13,54.35 C5.2 ; 54.61,80.39 R125.2 ; R125.2 55.12,80.9 ; R125.2 55.63,80.39 ; 8.4,45.11 R101.1 ; C59.2 40.35,35.93 ; C59.2 40.35,34.93 ; C59.2 40.78,35.43 ; 60.61,31.56 C18.2 ; C18.2 61.51,31.56 ; C18.2 61.06,31.14 ; 97.41,73.28 R41.2 96.9,72.77 ; U11.15 22.02,23.35 ; 15.64,67.61 C7.2 16.06,68.11 ; 36.45,60.84 C82.2 35.94,60.32 ; 8.48,16.36 R146.2 ; R146.2 9.5,16.36 ; R146.2 8.99,16.87 ; 54.09,97.22 R29.2 53.07,97.22 ; 39.62,77.09 R114.2 ; 94.1,72.77 C31.2 94.61,73.28 ; 25.3,81.16 C88.2 24.28,81.16 ; C28.2 98.42,73.28 ; 41.77,101.98 J19.3 ; J19.3 42.88,100.87 ; J19.3 42.88,103.09 ; U12.12 100.43,67.81 ; 42.62,96.52 U26.2 43.81,96.52 ; 19.66,28.24 R102.2 19.15,28.75 ; 23.95,20.5 C22.2 ; C22.2 24.97,20.5 ; C22.2 24.46,19.99 ; 37.62,30.48 J10.15 35.58,30.48 ; R109.2 20.83,39.75 ; 20.83,41.02 R108.2 20.83,42.04 ; 27.42,49.41 C93.2 27.42,50.44 ; 96.68,67.31 U12.3 ; 25.02,44.58 U22.8 ; U22.8 24.68,45.19 ; 24.44,86.65 C85.2 25.46,86.65 ; 95.63,73.28 C29.2 96.14,72.77 ; J1.5 5.07,60.29 ; 64.67,33.02 C467.2 64.22,33.44 ; 96.68,66.31 U12.5 ; R128.2 31.2,75.15 ; J32.11 55.31,46.63 ; 98.12,77.95 Q4.1 ; R40.2 103.51,62.48 ; C10.2 v2(11.58,73.4)
  TOP w0.381: U16.C8 v1(11.04,39.77) ; U16.D3 v1(11.84,34.97) ; C8.2 v2(19.94,64.01) ; U16.C2 v1(11.04,34.17) ; U16.D4 v1(11.84,35.77) ; U16.J6 v1(16.63,38.17) ; v1(11.84,36.57) U16.D5 12.63,37.37 ; U16.F2 v1(14.23,34.17) ; U16.G8 v1(15.03,39.77) ; v1(16.63,34.97) U16.J3 v1(15.84,35.77)
  TOP w0.508: C76.2 v2(11.84,27.89) ; U9.2 v2(49.63,93.34) ; R160.2 v2(99.61,75.59) ; R109.2 v2(21.59,39.24) ; SW2.4 v2(101.45,31.33) ; R165.2 v2(89.46,92.43) ; R39.2 v2(102.11,63.34) ; D11.2 v2(46.32,79.74) ; C34.2 v2(95.35,23.31) ; C85.2 v2(24.95,85.9) ; C74.2 v2(22.61,33.3) ; C72.2 v2(5.05,33.58) ; R120.2 v2(32.03,87.05) ; C92.2 v2(21.96,49.89) ; C73.2 v2(22.61,34.49) ; v2(101.43,15.26) 101.45,15.23 SW1.3 ; C70.2 v2(21.59,37.74) ; SW4.4 v2(101.45,42.39) ; C30.2 v2(99.44,60.99) ; SW2.3 v2(101.45,37.38) ; C5.2 v2(33.02,54.86) ; C33.2 v2(95.48,34.36) ; C88.2 v2(24.79,80.34) ; v2(52.07,97.9) C23.2 ; U1.1 v2(33.75,58.79) ; R163.2 v2(99.39,82.04) ; R159.2 v2(45.57,89.53) ; R121.2 v2(51.77,85.85) ; R115.2 v2(39.34,74.42) ; R128.2 v2(31.98,74.64) ; C98.2 v2(95.48,45.47) ; v2(3.51,16.15) J16.3 ; C86.2 v2(32.03,88.09) ; C93.2 v2(28.56,49.93) ; C3.2 34.98,66.11 34.54,66.55 v2(33.91,66.55) ; C58.2 v2(79.78,47.24) ; U21.2 v2(25.58,74.69) ; v2(3.51,14.88) J16.5 ; C32.2 v2(95.48,12.19) ; C87.2 v2(31.93,82.93) ; C81.2 v2(2.41,15.47) ; C95.2 v2(11.56,10.16) ; R101.1 v2(8.92,46.43) ; J17.3 v2(52.32,75.18) ; SW3.4 101.45,20.3 v2(101.43,20.27) ; C71.2 v2(14.33,45.95) ; R40.2 v2(103,63.34) ; R107.2 v2(21.59,40.39) ; v2(6.55,59.23) L2.2 ; 59.94,45.21 v1(59.94,45.22) J32.65 ; SW3.3 101.45,26.29 v2(101.43,26.32) ; 62.48,47.88 J32.65 ; J32.65 57.28,47.88 ; C1.2 v2(8.06,65.35) ; C84.2 v2(45.97,78.11) ; v2(11.05,17.4) 10.03,17.4 R146.2 ; R108.2 v2(21.59,41.53) ; L7.2 v2(60.07,101.07) ; R99.1 v2(22.61,31.04) ; C78.2 v2(12.9,27.89) ; v2(53.58,97.97) R29.2 ; R110.2 v2(13.11,45.95) ; R114.2 v2(40.13,78.11) ; C91.2 v2(32,76) ; C69.2 v2(5.11,36.96) ; SW4.3 v2(101.45,48.44) ; J17.5 v2(52.32,76.45)
  L2_GND_1 w0.254: SS1.1 5.08,8.07 ; SS1.1 5.08,2.09 ; SS1.1 2.09,5.08 ; SS1.1 8.07,5.08 ; 13.05,2.79 J18.10 ; J18.10 15.08,2.79 ; J18.10 14.06,3.81 ; J18.10 14.06,1.77 ; 21.97,58.23 JS1.2 ; JS1.2 22.93,59.18 ; JS1.2 21.97,60.14 ; JS1.2 21.02,59.18 ; J10.17 36.6,28.96 ; J10.17 36.6,26.92 ; J10.17 37.62,27.94 ; J10.17 35.58,27.94 ; J18.9 15.08,5.33 ; J18.9 13.05,5.33 ; J18.9 14.06,6.35 ; J18.9 14.06,4.31 ; J8.8 49.29,25.21 ; J8.8 49.29,23.12 ; J8.8 50.34,24.17 ; J8.8 48.25,24.17 ; J9.8 84.86,45.72 ; J9.8 85.88,44.7 ; J9.8 83.84,44.7 ; J9.8 84.86,43.68 ; 97.09,5.08 SS2.1 ; SS2.1 103.06,5.08 ; SS2.1 100.08,2.09 ; SS2.1 100.08,8.07 ; 36.6,29.46 J10.15 ; J10.15 35.58,30.48 ; J10.15 36.6,31.5 ; J10.15 37.62,30.48 ; J19.3 42.88,103.09 ; J19.3 41.77,101.98 ; J19.3 43.98,101.98 ; J19.3 42.88,100.87 ; 8.52,52.3 JP6.2 ; JP6.2 9.47,51.34 ; JP6.2 9.47,53.25 ; JP6.2 10.43,52.3 ; JP4.2 30.29,14.22 ; JP4.2 29.34,15.18 ; JP4.2 28.38,14.22 ; JP4.2 29.34,13.27 ; 92.96,8.34 J11.4 ; J11.4 92.96,10.46 ; J11.4 94.02,9.4 ; J11.4 91.91,9.4 ; 2.09,107.82 SS3.1 ; SS3.1 5.08,104.83 ; SS3.1 8.07,107.82 ; SS3.1 5.08,110.81 ; 97.09,107.82 SS4.1 ; SS4.1 100.08,110.81 ; SS4.1 103.06,107.82 ; SS4.1 100.08,104.83 ; 72.15,23.12 J7.8 ; J7.8 71.11,24.17 ; J7.8 73.2,24.17 ; J7.8 72.15,25.21 ; 93.6,48.57 JS3.2 ; JS3.2 92.64,49.53 ; JS3.2 94.55,49.53 ; JS3.2 93.6,50.49 ; J3.3 30.29,22.35 ; J3.3 29.34,23.31 ; J3.3 29.34,21.4 ; J3.3 28.38,22.35
  BOTTOM w0.254: J18.10 15.08,2.79 ; J18.10 14.06,3.81 ; J18.10 14.06,1.77 ; J18.10 13.05,2.79 ; 21.97,58.23 JS1.2 ; JS1.2 21.97,60.14 ; JS1.2 21.02,59.18 ; 36.6,26.92 J10.17 ; J10.17 36.6,28.96 ; J10.17 35.58,27.94 ; J10.17 37.62,27.94 ; SS2.1 103.06,5.08 ; SS2.1 100.08,2.09 ; SS2.1 100.08,8.07 ; SS2.1 97.09,5.08 ; J10.15 37.62,30.48 ; J10.15 36.6,29.46 ; J10.15 35.58,30.48 ; J10.15 36.6,31.5 ; C448.2 59.88,53.97 ; C448.2 59.44,54.39 ; C448.2 58.99,53.97 ; 72.15,23.12 J7.8 ; J7.8 71.11,24.17 ; J7.8 72.15,25.21 ; J7.8 73.2,24.17 ; 48.25,24.17 J8.8 ; J8.8 49.29,25.21 ; J8.8 50.34,24.17 ; J8.8 49.29,23.12 ; 92.64,49.53 JS3.2 ; JS3.2 93.6,48.57 ; JS3.2 93.6,50.49 ; JS3.2 94.55,49.53 ; 91.91,9.4 J11.4 ; J11.4 92.96,10.46 ; J11.4 94.02,9.4 ; J11.4 92.96,8.34 ; 84.86,45.72 J9.8 85.88,44.7 ; J3.3 30.29,22.35 ; J3.3 29.34,23.31 ; J3.3 29.34,21.4 ; J3.3 28.38,22.35 ; 2.09,5.08 SS1.1 ; SS1.1 5.08,2.09 ; SS1.1 5.08,8.07 ; SS1.1 8.07,5.08 ; SS3.1 8.07,107.82 ; SS3.1 2.09,107.82 ; SS3.1 5.08,104.83 ; SS3.1 5.08,110.81 ; 60.97,42.1 C450.2 C447.2 60.97,40.07 ; J19.3 43.98,101.98 ; J19.3 41.77,101.98 ; J19.3 42.88,100.87 ; J19.3 42.88,103.09 ; 14.06,4.31 J18.9 ; J18.9 14.06,6.35 ; J18.9 15.08,5.33 ; J18.9 13.05,5.33 ; C468.2 51.18,49.82 ; C468.2 50.73,49.4 ; C468.2 51.63,49.4 ; 100.08,104.83 SS4.1 ; SS4.1 103.06,107.82 ; SS4.1 97.09,107.82 ; SS4.1 100.08,110.81 ; 60.13,53.97 C449.2 61.03,53.97 ; 54.29,47.38 C451.2 ; C451.2 55.18,47.38 ; C451.2 54.74,46.95 ; 29.34,13.27 JP4.2 ; JP4.2 30.29,14.22 ; JP4.2 28.38,14.22 ; JP4.2 29.34,15.18 ; 65.4,47.4 C446.2 64.9,46.98 ; 7.04,62.51 U2.7 7.04,60.83
  vias: v1(5.19,26.82) v1(6.68,26.82) v1(7.98,31.42) v1(8.03,30.02) v1(8.03,28.24) v1(9.78,30.02) v1(9.78,28.24) v1(10.69,31.42) v1(11,26.87) v1(21.08,90.17) v1(22.35,91.06) v1(40.13,43.81) v1(41.15,44.07) v1(48.77,43.94) v1(48.89,53.47) v1(49.02,50.67) v1(50.16,53.47) v1(50.67,50.8) v1(58.29,44.7) v1(58.29,43.69) v1(58.42,45.59) v1(62.1,45.09) v1(62.48,46.86) v1(62.48,40.51) v1(64.64,32.26) v1(69.6,35.69) v1(72.39,31.62) v1(74.04,38.48) v1(74.3,20.7) v1(74.42,35.81) v1(74.42,31.62) v1(76.71,20.45) v1(77.34,30.1) v1(77.34,21.34) v1(77.47,19.69) v1(89.66,65.91) v1(90.8,65.91) v1(92.96,65.91) v1(94.36,65.91) v1(100.08,32.45) v1(100.2,35.5) v1(100.2,33.72) v1(100.2,20.9) v1(100.33,24.96) v1(100.33,23.31) v1(100.33,13.84) v1(100.33,12.32) v1(100.33,10.54) v2(11.05,27.89) v2(12.95,17.78) v2(19.81,11.94) v2(20.57,78.99) v2(23.75,76.71) v2(26.03,29.21) v2(47.45,97.69) v2(48.46,97.69) v2(97.49,77.95) v2(99.57,79.25)
